
// ===== library: MasterCopy "SIKO_AG24_Tags_1" =====

VAR_GLOBAL   // PLC tag table "SIKO_AG24_Tags_1"
   "Drive1TargetValue" AT %QD2 : DWord;
   "Drive1ControlWord" AT %QW6 : Word;
   "Drive1DigitalOutputsControl" AT %QW8 : Word;
   "Drive1ActualValue" AT %ID2 : DWord;
   "Drive1GenericMappingChannel" AT %ID6 : DWord;
   "Drive1StatusWord" AT %IW10 : Word;
   "Drive1DigitalInputsState" AT %IW12 : Word;
END_VAR

// ===== library: MasterCopy "SIKO_AG24" =====

FUNCTION_BLOCK "SIKO_AG24"   // FB401, SCL
TITLE = SIKO_AG24
{ S7_Optimized_Access := 'FALSE' }
AUTHOR : SIKO_ch
FAMILY : AG24
NAME : 1.00
VERSION : 1.00
// Usable with AG24 Firmware Vers. A/V >= V1.06
   VAR_INPUT
      nTargetValue : DInt;
      bc00_Off1 : Bool;
      bc01_Off2 : Bool;
      bc02_Off3 : Bool;
      bc03_IntermediateStop : Bool;
      bc04_StartTravelJob : Bool;
      bc05_AckError : Bool;
      bc06_InchingMode1 : Bool;
      bc07_Inching2Pos : Bool;
      bc08_Inching2Neg : Bool;
      bc09_KeyEnable : Bool;
      bc10_MoveRelative : Bool;
      bc11 : Bool;
      bc12 : Bool;
      bc13 : Bool;
      bc14 : Bool;
      bc15_Cal : Bool;
      bcDigitalOutput1 : Bool;
      DC_nHwId : Hw_Io;
      DC_nStatusWord : Word;
      varrStatusWord AT DC_nStatusWord : Array[0..15] of Bool;
      DC_nActualValue : DWord;
      DC_nGenMapCh : DWord;
      DC_nDigitalInputsState : Word;
      varrDigitalInputsState AT DC_nDigitalInputsState : Array[0..15] of Bool;
      bcStartRead : Bool;
      bcStartWrite : Bool;
      bcStartCopy : Bool;
   END_VAR
   VAR_OUTPUT
      nActualValue : DInt;
      bs00_Supply : Bool;
      bs01_ReadinessToTravel : Bool;
      bs02_UpperLimit : Bool;
      bs03_LowerLimit : Bool;
      bs04_ActuatorTravels : Bool;
      bs05_InPos : Bool;
      bs06_ActiveTravelJob : Bool;
      bs07_Error : Bool;
      bs08_OperationEnabled : Bool;
      bs09_SwitchLock : Bool;
      bs10_TravelJobAck : Bool;
      bs11 : Bool;
      bs12_CurrentLimiting : Bool;
      bs13_LimitSwitch1 : Bool;
      bs14_LimitSwitch2 : Bool;
      bs15_CalAck : Bool;
      bsDigitalInput1 : Bool;
      bsDigitalInput2 : Bool;
      bsDigitalInput3 : Bool;
      bsDigitalInput4 : Bool;
      nGenMapCh : DInt;
      DC_nControlWord : Word;
      varrControlWord AT DC_nControlWord : Array[0..15] of Bool;
      DC_nTargetValue : DWord;
      DC_nDigitalOutputsControl : Word;
      varrDigitalOutputControl AT DC_nDigitalOutputsControl : Array[0..15] of Bool;
      bsBusy : Bool;
      bsError : Bool;
      bsDone : Bool;
      nStatus : DWord;
      nCounterRead : UInt;
      nCounterWrite : UInt;
      nCounterCopy : UInt;
   END_VAR
   VAR
      DC_DataBuffer : DWord;
      varrDataBuffer AT DC_DataBuffer : Array[0..3] of Byte;
      vbOsfReadBusy : Bool;
      vbMemReadBusy : Bool;
      vbOsfWriteBusy : Bool;
      vbMemWriteBusy : Bool;
      vbOsrStartRead : Bool;
      vbMemStartRead : Bool;
      vbOsrStartWrite : Bool;
      vbMemStartWrite : Bool;
      vbOsrStartCopy : Bool;
      vbMemStartCopy : Bool;
      vnReadCounter : UInt;
      vnWriteCounter : UInt;
      vnCopyCounter : UInt;
      fbRDREC1 : RDREC;
      vbReadValid : Bool;
      vbReadBusy : Bool;
      vbReadError : Bool;
      vnReadStatus : DWord;
      vnReadIndex : DInt;
      vbReadEnable : Bool;
      vnReadLength : UInt;
      vnReadState : UInt;
      fbWRREC_1 : WRREC;
      vbWriteDone : Bool;
      vbWriteBusy : Bool;
      vbWriteError : Bool;
      vnWriteStatus : DWord;
      vnWriteIndex : DInt;
      vbWriteEnable : Bool;
      vnWriteLength : UInt;
      vnWriteState : UInt;
      vnCopyState : UInt;
      p0221_ServiceInterfaceBaudRate_r : USInt;
      p0221_ServiceInterfaceBaudRate_w : USInt := 1;
      p0222_GenMapParam_r : USInt;
      p0222_GenMapParam_w : USInt := 0;
      p0241_PeakCurrentLimit_r : Int;
      p0241_PeakCurrentLimit_w : Int := 12000;
      p0242_PeakCurrentTime_r : Int;
      p0242_PeakCurrentTime_w : Int := 40;
      p0243_ContinuousCurrent_r : Int;
      p0243_ContinuousCurrent_w : Int := 7500;
      p0301_DigitalOutput1Functionality_r : USInt;
      p0301_DigitalOutput1Functionality_w : USInt := 0;
      p0302_DigitalOutputFunctionalitiesState_r : UDInt;
      p0303_DigitalOutputsPolarity_r : USInt;
      p0303_DigitalOutputsPolarity_w : USInt := 0;
      p0401_DigitalInput1Functionality_r : USInt;
      p0401_DigitalInput1Functionality_w : USInt := 0;
      p0402_DigitalInput2Functionality_r : USInt;
      p0402_DigitalInput2Functionality_w : USInt := 0;
      p0403_DigitalInput3Functionality_r : USInt;
      p0403_DigitalInput3Functionality_w : USInt := 0;
      p0404_DigitalInput4Functionality_r : USInt;
      p0404_DigitalInput4Functionality_w : USInt := 0;
      p0405_DigitalInputFunctionalitiesState_r : UDInt;
      p0406_DigitalInputsPolarity_r : USInt;
      p0406_DigitalInputsPolarity_w : USInt := 0;
      p0601_ControllerParameterP_r : Int;
      p0601_ControllerParameterP_w : Int := 300;
      p0602_ControllerParameterI_r : Int;
      p0602_ControllerParameterI_w : Int := 2;
      p0603_ControllerParameterD_r : Int;
      p0603_ControllerParameterD_w : Int := 0;
      p0604_APos_r : Int;
      p0604_APos_w : Int := 50;
      p0605_VPos_r : Int;
      p0605_VPos_w : Int := 10;
      p0606_DPos_r : Int;
      p0606_DPos_w : Int := 101;
      p0607_ARot_r : Int;
      p0607_ARot_w : Int := 50;
      p0608_AInch_r : Int;
      p0608_AInch_w : Int := 50;
      p0609_VInch_r : Int;
      p0609_VInch_w : Int := 10;
      p060A_PosWindow_r : Int;
      p060A_PosWindow_w : Int := 10;
      p060B_GearRatioNumerator_r : Int;
      p060B_GearRatioNumerator_w : Int := 1;
      p060C_GearRatioDenominator_r : Int;
      p060C_GearRatioDenominator_w : Int := 1;
      p060D_SpindlePitch_r : DInt;
      p060D_SpindlePitch_w : DInt := 0;
      p060E_CalibrationValue_r : DInt;
      p060E_CalibrationValue_w : DInt := 0;
      p060F_SoftwareLimit1_r : DInt;
      p060F_SoftwareLimit1_w : DInt := 999999;
      p0610_SoftwareLimit2_r : DInt;
      p0610_SoftwareLimit2_w : DInt := -199999;
      p0611_DeltaInch_r : DInt;
      p0611_DeltaInch_w : DInt := 1024;
      p0612_SenseOfRotation_r : USInt;
      p0612_SenseOfRotation_w : USInt := 0;
      p0613_PosType_r : USInt;
      p0613_PosType_w : USInt := 0;
      p0614_OperatingMode_r : USInt;
      p0614_OperatingMode_w : USInt := 0;
      p0615_Inching2StopMode_r : USInt;
      p0615_Inching2StopMode_w : USInt := 0;
      p0616_InposMode_r : USInt;
      p0616_InposMode_w : USInt := 0;
      p0617_LoopLength_r : Int;
      p0617_LoopLength_w : Int := 512;
      p0618_ContouringErrorLimit_r : Int;
      p0618_ContouringErrorLimit_w : Int := 1024;
      p061A_Inching2Offset_r : USInt;
      p061A_Inching2Offset_w : USInt := 100;
      p061B_Inching2AccelerationType_r : USInt;
      p061B_Inching2AccelerationType_w : USInt := 0;
      p061C_OffsetValue_r : DInt;
      p061C_OffsetValue_w : DInt := 0;
      p0701_DisplayDivisor_r : USInt;
      p0701_DisplayDivisor_w : USInt := 0;
      p0702_DisplayDivisorApplication_r : USInt;
      p0702_DisplayDivisorApplication_w : USInt := 0;
      p0703_DisplayOrientation_r : USInt;
      p0703_DisplayOrientation_w : USInt := 0;
      p0704_DecimalPlaces_r : USInt;
      p0704_DecimalPlaces_w : USInt := 0;
      p0705_DirectionIndicationFunction_r : USInt;
      p0705_DirectionIndicationFunction_w : USInt := 0;
      p0706_Display2ndLine_r : USInt;
      p0706_Display2ndLine_w : USInt := 0;
      p0707_KeyEnableTime_r : USInt;
      p0707_KeyEnableTime_w : USInt := 3;
      p0708_KeyFunctionEnable_r : USInt;
      p0708_KeyFunctionEnable_w : USInt := 0;
      p0709_PinChange_r : DInt;
      p0709_PinChange_w : DInt := 0;
      p0801_TalTrigger_r : Int;
      p0801_TalTrigger_w : Int := 0;
      p0802_TalDirection_r : USInt;
      p0802_TalDirection_w : USInt := 0;
      p0922_PcmPosition1_r : DInt;
      p0922_PcmPosition1_w : DInt := 0;
      p0923_PcmPosition2_r : DInt;
      p0923_PcmPosition2_w : DInt := 0;
      p0924_PcmPosition3_r : DInt;
      p0924_PcmPosition3_w : DInt := 0;
      p0925_PcmPosition4_r : DInt;
      p0925_PcmPosition4_w : DInt := 0;
      p0926_PcmPosition5_r : DInt;
      p0926_PcmPosition5_w : DInt := 0;
      p0927_PcmPosition6_r : DInt;
      p0927_PcmPosition6_w : DInt := 0;
      p0928_PcmPosition7_r : DInt;
      p0928_PcmPosition7_w : DInt := 0;
      p0942_PcmAcceleration1_r : Int;
      p0942_PcmAcceleration1_w : Int := 50;
      p0943_PcmAcceleration2_r : Int;
      p0943_PcmAcceleration2_w : Int := 50;
      p0944_PcmAcceleration3_r : Int;
      p0944_PcmAcceleration3_w : Int := 50;
      p0945_PcmAcceleration4_r : Int;
      p0945_PcmAcceleration4_w : Int := 50;
      p0946_PcmAcceleration5_r : Int;
      p0946_PcmAcceleration5_w : Int := 50;
      p0947_PcmAcceleration6_r : Int;
      p0947_PcmAcceleration6_w : Int := 50;
      p0948_PcmAcceleration7_r : Int;
      p0948_PcmAcceleration7_w : Int := 50;
      p0962_PcmVelocity1_r : Int;
      p0962_PcmVelocity1_w : Int := 10;
      p0963_PcmVelocity2_r : Int;
      p0963_PcmVelocity2_w : Int := 10;
      p0964_PcmVelocity3_r : Int;
      p0964_PcmVelocity3_w : Int := 10;
      p0965_PcmVelocity4_r : Int;
      p0965_PcmVelocity4_w : Int := 10;
      p0966_PcmVelocity5_r : Int;
      p0966_PcmVelocity5_w : Int := 10;
      p0967_PcmVelocity6_r : Int;
      p0967_PcmVelocity6_w : Int := 10;
      p0968_PcmVelocity7_r : Int;
      p0968_PcmVelocity7_w : Int := 10;
      p0982_PcmDeceleration1_r : Int;
      p0982_PcmDeceleration1_w : Int := 101;
      p0983_PcmDeceleration2_r : Int;
      p0983_PcmDeceleration2_w : Int := 101;
      p0984_PcmDeceleration3_r : Int;
      p0984_PcmDeceleration3_w : Int := 101;
      p0985_PcmDeceleration4_r : Int;
      p0985_PcmDeceleration4_w : Int := 101;
      p0986_PcmDeceleration5_r : Int;
      p0986_PcmDeceleration5_w : Int := 101;
      p0987_PcmDeceleration6_r : Int;
      p0987_PcmDeceleration6_w : Int := 101;
      p0988_PcmDeceleration7_r : Int;
      p0988_PcmDeceleration7_w : Int := 101;
      p0A01_OutputStageTemperature_r : Int;
      p0A02_VoltageOfControl_r : Int;
      p0A03_VoltageOfOutputStage_r : Int;
      p0A05_MotorCurrent_r : Int;
      p0A06_ActualPosition_r : DInt;
      p0A07_ActualRotationalSpeed_r : Int;
      p0A08_SerialNumber_r : DInt;
      p0A09_ProductionDate_r : DInt;
      p0A0A_SwMotorController_r : DInt;
      p0A0B_GearReduction_r : Int;
      p0A0C_SystemStatusWord_r : UInt;
      p0A0D_EncoderResolution_r : Int;
      p0A0E_DeviceId_r : USInt;
      p0A0F_VirtualMotorTemperature_r : Int;
      p0A10_OutputStageOverload_r : USInt;
      p0A11_ActualContouringError_r : DInt;
      p0B01_NumberOfErrors_r : USInt;
      p0B02_ErrorNumber1_r : USInt;
      p0B03_ErrorNumber2_r : USInt;
      p0B04_ErrorNumber3_r : USInt;
      p0B05_ErrorNumber4_r : USInt;
      p0B06_ErrorNumber5_r : USInt;
      p0B07_ErrorNumber6_r : USInt;
      p0B08_ErrorNumber7_r : USInt;
      p0B09_ErrorNumber8_r : USInt;
      p0B0A_ErrorNumber9_r : USInt;
      p0B0B_ErrorNumber10_r : USInt;
      p0B21_Configuration_r : UInt;
      p0B21_Configuration_w : UInt := 15;
      p0C01_Scommand_r : USInt;
      p0C01_Scommand_w : USInt := 0;
   END_VAR
BEGIN
   ////////////////////////////////////////////////////////////////////////////////////
   // Version history
   ////////////////////////////////////////////////////////////////////////////////////
   // Date        | Vers. | created               | Author          | Remark
   // dd.mm.yyyy  |       | with                  |                 | 
   // ---------------------------------------------------------------------------------
   // 01.08.2017  | 0.01  | TIA V13 SP1           | SIKO GmbH / ch  | alpha
   // 02.08.2017  | 0.02  | TIA V13 SP1           | SIKO GmbH / ch  | beta
   // 10.08.2017  | 0.03  | TIA V13 SP1           | SIKO GmbH / ch  | RC
   // 28.06.2018  | 1.00  | TIA V14 SP1 Upd5      | SIKO GmbH / ch  | Release
   ////////////////////////////////////////////////////////////////////////////////////

   // Actual Value
   #nActualValue := DWORD_TO_DINT(IN := #DC_nActualValue);

   // Generic Mapping Channel
   #nGenMapCh := DWORD_TO_DINT(IN := #DC_nGenMapCh);

   // Status Word Bits
   #bs00_Supply := #varrStatusWord[8];
   #bs01_ReadinessToTravel := #varrStatusWord[9];
   #bs02_UpperLimit := #varrStatusWord[10];
   #bs03_LowerLimit := #varrStatusWord[11];
   #bs04_ActuatorTravels := #varrStatusWord[12];
   #bs05_InPos := #varrStatusWord[13];
   #bs06_ActiveTravelJob := #varrStatusWord[14];
   #bs07_Error := #varrStatusWord[15];
   #bs08_OperationEnabled := #varrStatusWord[0];
   #bs09_SwitchLock := #varrStatusWord[1];
   #bs10_TravelJobAck := #varrStatusWord[2];
   #bs11 := #varrStatusWord[3];
   #bs12_CurrentLimiting := #varrStatusWord[4];
   #bs13_LimitSwitch1 := #varrStatusWord[5];
   #bs14_LimitSwitch2 := #varrStatusWord[6];
   #bs15_CalAck := #varrStatusWord[7];

   // Digital Inputs Status Bits
   #bsDigitalInput1 := #varrDigitalInputsState[8];
   #bsDigitalInput2 := #varrDigitalInputsState[9];
   #bsDigitalInput3 := #varrDigitalInputsState[10];
   #bsDigitalInput4 := #varrDigitalInputsState[11];

   // Target Value
   #DC_nTargetValue := DINT_TO_DWORD(IN := #nTargetValue);

   // Control Word Bits 
   #varrControlWord[8] := #bc00_Off1;
   #varrControlWord[9] := #bc01_Off2;
   #varrControlWord[10] := #bc02_Off3;
   #varrControlWord[11] := #bc03_IntermediateStop;
   #varrControlWord[12] := #bc04_StartTravelJob;
   #varrControlWord[13] := #bc05_AckError;
   #varrControlWord[14] := #bc06_InchingMode1;
   #varrControlWord[15] := #bc07_Inching2Pos;
   #varrControlWord[0] := #bc08_Inching2Neg;
   #varrControlWord[1] := #bc09_KeyEnable;
   #varrControlWord[2] := #bc10_MoveRelative;
   #varrControlWord[3] := #bc11;
   #varrControlWord[4] := #bc12;
   #varrControlWord[5] := #bc13;
   #varrControlWord[6] := #bc14;
   #varrControlWord[7] := #bc15_Cal;

   // Digital Output Control Bit 
   #varrDigitalOutputControl[8] := #bcDigitalOutput1;

   // Handle Parameter Read Command
   CASE #vnReadState OF
     0: // wait for rising edge at input bcStartRead
       IF #vbOsrStartRead AND (#vnWriteState = 0) AND (#vnCopyState = 0) THEN
         #bsBusy := TRUE;
         #bsError := FALSE;
         #bsDone := FALSE;
         #nStatus := 0;
         #nCounterRead := 0;
         #vnReadCounter := 0;
         #vnReadState := 1;
       END_IF;
     1: // Start RDREC
       #vnReadCounter := #vnReadCounter + 1;
       IF (#vnReadCounter > 109) THEN
       (* end of read cycle *)
         #bsBusy := FALSE;
         #bsError := FALSE;
         #bsDone := TRUE;
         #nStatus := 0;
         #nCounterRead := 0;
         #vnReadCounter := 0;
         #vnReadState := 0;
       ELSE
       (* output counter_read *)
         #nCounterRead := #vnReadCounter;
         CASE #vnReadCounter OF
           1:  (* p0221_ServiceInterfaceBaudrate *)
             #vnReadIndex := 545;
             #vbReadEnable := TRUE;
           2:  (* p0222_GenMapParam *)
             #vnReadIndex := 546;
             #vbReadEnable := TRUE;
           3:  (* p0241_PeakCurrentLimit *)
             #vnReadIndex := 577;
             #vbReadEnable := TRUE;
           4:  (* p0242_PeakCurrentTime *)
             #vnReadIndex := 578;
             #vbReadEnable := TRUE;
           5:  (* p0243_ContinuousCurrent *)
             #vnReadIndex := 579;
             #vbReadEnable := TRUE;
           6:  (* p0301_DigitalOutput1Functionality *)
             #vnReadIndex := 769;
             #vbReadEnable := TRUE;
           7:  (* p0302_DigitalOutputFunctionalitiesState *)
             #vnReadIndex := 770;
             #vbReadEnable := TRUE;
           8:  (* p0303_DigitalOutputsPolarity *)
             #vnReadIndex := 771;
             #vbReadEnable := TRUE;
           9:  (* p0401_DigitalInput1Functionality *)
             #vnReadIndex := 1025;
             #vbReadEnable := TRUE;
           10:  (* p0402_DigitalInput2Functionality *)
             #vnReadIndex := 1026;
             #vbReadEnable := TRUE;
           11:  (* p0403_DigitalInput3Functionality *)
             #vnReadIndex := 1027;
             #vbReadEnable := TRUE;
           12:  (* p0404_DigitalInput4Functionality *)
             #vnReadIndex := 1028;
             #vbReadEnable := TRUE;
           13:  (* p0405_DigitalInputFunctionalitiesState *)
             #vnReadIndex := 1029;
             #vbReadEnable := TRUE;
           14:  (* p0406_DigitalInputsPolarity *)
             #vnReadIndex := 1030;
             #vbReadEnable := TRUE;
           15:  (* p0601_ControllerParameterP *)
             #vnReadIndex := 1537;
             #vbReadEnable := TRUE;
           16:  (* p0602_ControllerParameterI *)
             #vnReadIndex := 1538;
             #vbReadEnable := TRUE;
           17:  (* p0603_ControllerParameterD *)
             #vnReadIndex := 1539;
             #vbReadEnable := TRUE;
           18:  (* p0604_APos *)
             #vnReadIndex := 1540;
             #vbReadEnable := TRUE;
           19:  (* p0605_VPos *)
             #vnReadIndex := 1541;
             #vbReadEnable := TRUE;
           20:  (* p0606_DPos *)
             #vnReadIndex := 1542;
             #vbReadEnable := TRUE;
           21:  (* p0607_ARot *)
             #vnReadIndex := 1543;
             #vbReadEnable := TRUE;
           22:  (* p0608_AInch *)
             #vnReadIndex := 1544;
             #vbReadEnable := TRUE;
           23:  (* p0609_VInch *)
             #vnReadIndex := 1545;
             #vbReadEnable := TRUE;
           24:  (* p060A_PosWindow *)
             #vnReadIndex := 1546;
             #vbReadEnable := TRUE;
           25:  (* p060B_GearRatioNumerator *)
             #vnReadIndex := 1547;
             #vbReadEnable := TRUE;
           26:  (* p060C_GearRatioDenominator *)
             #vnReadIndex := 1548;
             #vbReadEnable := TRUE;
           27:  (* p060D_SpindlePitch *)
             #vnReadIndex := 1549;
             #vbReadEnable := TRUE;
           28:  (* p060E_CalibrationValue *)
             #vnReadIndex := 1550;
             #vbReadEnable := TRUE;
           29:  (* p060F_SoftwareLimit1 *)
             #vnReadIndex := 1551;
             #vbReadEnable := TRUE;
           30:  (* p0610_SoftwareLimit2 *)
             #vnReadIndex := 1552;
             #vbReadEnable := TRUE;
           31:  (* p0611_DeltaInch *)
             #vnReadIndex := 1553;
             #vbReadEnable := TRUE;
           32:  (* p0612_SenseOfRotation *)
             #vnReadIndex := 1554;
             #vbReadEnable := TRUE;
           33:  (* p0613_PosType *)
             #vnReadIndex := 1555;
             #vbReadEnable := TRUE;
           34:  (* p0614_OperatingMode *)
             #vnReadIndex := 1556;
             #vbReadEnable := TRUE;
           35:  (* p0615_Inching2StopMode *)
             #vnReadIndex := 1557;
             #vbReadEnable := TRUE;
           36:  (* p0616_InposMode *)
             #vnReadIndex := 1558;
             #vbReadEnable := TRUE;
           37:  (* p0617_LoopLength *)
             #vnReadIndex := 1559;
             #vbReadEnable := TRUE;
           38:  (* p0618_ContouringErrorLimit *)
             #vnReadIndex := 1560;
             #vbReadEnable := TRUE;
           39:  (* p061A_Inching2Offset *)
             #vnReadIndex := 1562;
             #vbReadEnable := TRUE;
           40:  (* p061B_Inching2AccelerationType *)
             #vnReadIndex := 1563;
             #vbReadEnable := TRUE;
           41:  (* p061C_OffsetValue *)
             #vnReadIndex := 1564;
             #vbReadEnable := TRUE;
           42:  (* p0701_DisplayDivisor *)
             #vnReadIndex := 1793;
             #vbReadEnable := TRUE;
           43:  (* p0702_DisplayDivisorApplication *)
             #vnReadIndex := 1794;
             #vbReadEnable := TRUE;
           44:  (* p0703_DisplayOrientation *)
             #vnReadIndex := 1795;
             #vbReadEnable := TRUE;
           45:  (* p0704_DecimalPlaces *)
             #vnReadIndex := 1796;
             #vbReadEnable := TRUE;
           46:  (* p0705_DirectionIndicationFunction *)
             #vnReadIndex := 1797;
             #vbReadEnable := TRUE;
           47:  (* p0706_Display2ndLine *)
             #vnReadIndex := 1798;
             #vbReadEnable := TRUE;
           48:  (* p0707_KeyEnableTime *)
             #vnReadIndex := 1799;
             #vbReadEnable := TRUE;
           49:  (* p0708_KeyFunctionEnable *)
             #vnReadIndex := 1800;
             #vbReadEnable := TRUE;
           50:  (* p0709_PinChange *)
             #vnReadIndex := 1801;
             #vbReadEnable := TRUE;
           51:  (* p0801_TalTrigger *)
             #vnReadIndex := 2049;
             #vbReadEnable := TRUE;
           52:  (* p0802_TalDirection *)
             #vnReadIndex := 2050;
             #vbReadEnable := TRUE;
           53:  (* p0922_PcmPosition1 *)
             #vnReadIndex := 2338;
             #vbReadEnable := TRUE;
           54:  (* p0923_PcmPosition2 *)
             #vnReadIndex := 2339;
             #vbReadEnable := TRUE;
           55:  (* p0924_PcmPosition3 *)
             #vnReadIndex := 2340;
             #vbReadEnable := TRUE;
           56:  (* p0925_PcmPosition4 *)
             #vnReadIndex := 2341;
             #vbReadEnable := TRUE;
           57:  (* p0926_PcmPosition5 *)
             #vnReadIndex := 2342;
             #vbReadEnable := TRUE;
           58:  (* p0927_PcmPosition6 *)
             #vnReadIndex := 2343;
             #vbReadEnable := TRUE;
           59:  (* p0928_PcmPosition7 *)
             #vnReadIndex := 2344;
             #vbReadEnable := TRUE;
           60:  (* p0942_PcmAcceleration1 *)
             #vnReadIndex := 2370;
             #vbReadEnable := TRUE;
           61:  (* p0943_PcmAcceleration2 *)
             #vnReadIndex := 2371;
             #vbReadEnable := TRUE;
           62:  (* p0944_PcmAcceleration3 *)
             #vnReadIndex := 2372;
             #vbReadEnable := TRUE;
           63:  (* p0945_PcmAcceleration4 *)
             #vnReadIndex := 2373;
             #vbReadEnable := TRUE;
           64:  (* p0946_PcmAcceleration5 *)
             #vnReadIndex := 2374;
             #vbReadEnable := TRUE;
           65:  (* p0947_PcmAcceleration6 *)
             #vnReadIndex := 2375;
             #vbReadEnable := TRUE;
           66:  (* p0948_PcmAcceleration7 *)
             #vnReadIndex := 2376;
             #vbReadEnable := TRUE;
           67:  (* p0962_PcmVelocity1 *)
             #vnReadIndex := 2402;
             #vbReadEnable := TRUE;
           68:  (* p0963_PcmVelocity2 *)
             #vnReadIndex := 2403;
             #vbReadEnable := TRUE;
           69:  (* p0964_PcmVelocity3 *)
             #vnReadIndex := 2404;
             #vbReadEnable := TRUE;
           70:  (* p0965_PcmVelocity4 *)
             #vnReadIndex := 2405;
             #vbReadEnable := TRUE;
           71:  (* p0966_PcmVelocity5 *)
             #vnReadIndex := 2406;
             #vbReadEnable := TRUE;
           72:  (* p0967_PcmVelocity6 *)
             #vnReadIndex := 2407;
             #vbReadEnable := TRUE;
           73:  (* p0968_PcmVelocity7 *)
             #vnReadIndex := 2408;
             #vbReadEnable := TRUE;
           74:  (* p0982_PcmDeceleration1 *)
             #vnReadIndex := 2434;
             #vbReadEnable := TRUE;
           75:  (* p0983_PcmDeceleration2 *)
             #vnReadIndex := 2435;
             #vbReadEnable := TRUE;
           76:  (* p0984_PcmDeceleration3 *)
             #vnReadIndex := 2436;
             #vbReadEnable := TRUE;
           77:  (* p0985_PcmDeceleration4 *)
             #vnReadIndex := 2437;
             #vbReadEnable := TRUE;
           78:  (* p0986_PcmDeceleration5 *)
             #vnReadIndex := 2438;
             #vbReadEnable := TRUE;
           79:  (* p0987_PcmDeceleration6 *)
             #vnReadIndex := 2439;
             #vbReadEnable := TRUE;
           80:  (* p0988_PcmDeceleration7 *)
             #vnReadIndex := 2440;
             #vbReadEnable := TRUE;
           81:  (* p0A01_OutputStageTemperature *)
             #vnReadIndex := 2561;
             #vbReadEnable := TRUE;
           82:  (* p0A02_VoltageOfControl *)
             #vnReadIndex := 2562;
             #vbReadEnable := TRUE;
           83:  (* p0A03_VoltageOfOutputStage *)
             #vnReadIndex := 2563;
             #vbReadEnable := TRUE;
           84:  (* p0A05_MotorCurrent *)
             #vnReadIndex := 2565;
             #vbReadEnable := TRUE;
           85:  (* p0A06_ActualPosition *)
             #vnReadIndex := 2566;
             #vbReadEnable := TRUE;
           86:  (* p0A07_ActualRotationalSpeed *)
             #vnReadIndex := 2567;
             #vbReadEnable := TRUE;
           87:  (* p0A08_SerialNumber *)
             #vnReadIndex := 2568;
             #vbReadEnable := TRUE;
           88:  (* p0A09_ProductionDate *)
             #vnReadIndex := 2569;
             #vbReadEnable := TRUE;
           89:  (* p0A0A_SwMotorController *)
             #vnReadIndex := 2570;
             #vbReadEnable := TRUE;
           90:  (* p0A0B_GearReduction *)
             #vnReadIndex := 2571;
             #vbReadEnable := TRUE;
           91:  (* p0A0C_SystemStatusWord *)
             #vnReadIndex := 2572;
             #vbReadEnable := TRUE;
           92:  (* p0A0D_EncoderResolution *)
             #vnReadIndex := 2573;
             #vbReadEnable := TRUE;
           93:  (* p0A0E_DeviceId *)
             #vnReadIndex := 2574;
             #vbReadEnable := TRUE;
           94:  (* p0A0F_VirtualMotorTemperature *)
             #vnReadIndex := 2575;
             #vbReadEnable := TRUE;
           95:  (* p0A10_OutputStageOverload *)
             #vnReadIndex := 2576;
             #vbReadEnable := TRUE;
           96:  (* p0A11_ActualContouringError *)
             #vnReadIndex := 2577;
             #vbReadEnable := TRUE;
           97:  (* p0B01_NumberOfErrors *)
             #vnReadIndex := 2817;
             #vbReadEnable := TRUE;
           98:  (* p0B02_ErrorNumber1 *)
             #vnReadIndex := 2818;
             #vbReadEnable := TRUE;
           99:  (* p0B03_ErrorNumber2 *)
             #vnReadIndex := 2819;
             #vbReadEnable := TRUE;
           100:  (* p0B04_ErrorNumber3 *)
             #vnReadIndex := 2820;
             #vbReadEnable := TRUE;
           101:  (* p0B05_ErrorNumber4 *)
             #vnReadIndex := 2821;
             #vbReadEnable := TRUE;
           102:  (* p0B06_ErrorNumber5 *)
             #vnReadIndex := 2822;
             #vbReadEnable := TRUE;
           103:  (* p0B07_ErrorNumber6 *)
             #vnReadIndex := 2823;
             #vbReadEnable := TRUE;
           104:  (* p0B08_ErrorNumber7 *)
             #vnReadIndex := 2824;
             #vbReadEnable := TRUE;
           105:  (* p0B09_ErrorNumber8 *)
             #vnReadIndex := 2825;
             #vbReadEnable := TRUE;
           106:  (* p0B0A_ErrorNumber9 *)
             #vnReadIndex := 2826;
             #vbReadEnable := TRUE;
           107:  (* p0B0B_ErrorNumber10 *)
             #vnReadIndex := 2827;
             #vbReadEnable := TRUE;
           108:  (* p0B21_Configuration *)
             #vnReadIndex := 2849;
             #vbReadEnable := TRUE;
           109:  (* p0C01_Scommand *)
             #vnReadIndex := 3073;
             #vbReadEnable := TRUE;
         END_CASE;
         #vnReadState := 2;
       END_IF;
     2: // wait for end of RDREC
       IF #vbOsfReadBusy THEN
         #vnReadState := 3;
       END_IF;
     3: // Check for errors, copy output
       #vbReadEnable := FALSE;
       IF #vbReadError THEN
         #bsBusy := FALSE;
         #bsError := TRUE;
         #bsDone := FALSE;
         #nStatus := #vnReadStatus;
         #vnReadCounter := 0;
         #vnReadState := 0;
       ELSIF #vbReadValid THEN
       (* Data Valid *)
         #nStatus := #vnReadStatus;

         CASE #vnReadCounter OF
           1:
             #p0221_ServiceInterfaceBaudRate_r := DWORD_TO_USINT(SHR(IN := #DC_DataBuffer, N := 24));
           2:
             #p0222_GenMapParam_r := DWORD_TO_USINT(SHR(IN := #DC_DataBuffer, N := 24));
           3:
             #p0241_PeakCurrentLimit_r := DWORD_TO_INT(SHR(IN := #DC_DataBuffer, N := 16));
           4:
             #p0242_PeakCurrentTime_r := DWORD_TO_INT(SHR(IN := #DC_DataBuffer, N := 16));
           5:
             #p0243_ContinuousCurrent_r := DWORD_TO_INT(SHR(IN := #DC_DataBuffer, N := 16));
           6:
             #p0301_DigitalOutput1Functionality_r := DWORD_TO_USINT(SHR(IN := #DC_DataBuffer, N := 24));
           7:
             #p0302_DigitalOutputFunctionalitiesState_r := DWORD_TO_UDINT(SHR(IN := #DC_DataBuffer, N := 0));
           8:
             #p0303_DigitalOutputsPolarity_r := DWORD_TO_USINT(SHR(IN := #DC_DataBuffer, N := 24));
           9:
             #p0401_DigitalInput1Functionality_r := DWORD_TO_USINT(SHR(IN := #DC_DataBuffer, N := 24));
           10:
             #p0402_DigitalInput2Functionality_r := DWORD_TO_USINT(SHR(IN := #DC_DataBuffer, N := 24));
           11:
             #p0403_DigitalInput3Functionality_r := DWORD_TO_USINT(SHR(IN := #DC_DataBuffer, N := 24));
           12:
             #p0404_DigitalInput4Functionality_r := DWORD_TO_USINT(SHR(IN := #DC_DataBuffer, N := 24));
           13:
             #p0405_DigitalInputFunctionalitiesState_r := DWORD_TO_UDINT(SHR(IN := #DC_DataBuffer, N := 0));
           14:
             #p0406_DigitalInputsPolarity_r := DWORD_TO_USINT(SHR(IN := #DC_DataBuffer, N := 24));
           15:
             #p0601_ControllerParameterP_r := DWORD_TO_INT(SHR(IN := #DC_DataBuffer, N := 16));
           16:
             #p0602_ControllerParameterI_r := DWORD_TO_INT(SHR(IN := #DC_DataBuffer, N := 16));
           17:
             #p0603_ControllerParameterD_r := DWORD_TO_INT(SHR(IN := #DC_DataBuffer, N := 16));
           18:
             #p0604_APos_r := DWORD_TO_INT(SHR(IN := #DC_DataBuffer, N := 16));
           19:
             #p0605_VPos_r := DWORD_TO_INT(SHR(IN := #DC_DataBuffer, N := 16));
           20:
             #p0606_DPos_r := DWORD_TO_INT(SHR(IN := #DC_DataBuffer, N := 16));
           21:
             #p0607_ARot_r := DWORD_TO_INT(SHR(IN := #DC_DataBuffer, N := 16));
           22:
             #p0608_AInch_r := DWORD_TO_INT(SHR(IN := #DC_DataBuffer, N := 16));
           23:
             #p0609_VInch_r := DWORD_TO_INT(SHR(IN := #DC_DataBuffer, N := 16));
           24:
             #p060A_PosWindow_r := DWORD_TO_INT(SHR(IN := #DC_DataBuffer, N := 16));
           25:
             #p060B_GearRatioNumerator_r := DWORD_TO_INT(SHR(IN := #DC_DataBuffer, N := 16));
           26:
             #p060C_GearRatioDenominator_r := DWORD_TO_INT(SHR(IN := #DC_DataBuffer, N := 16));
           27:
             #p060D_SpindlePitch_r := DWORD_TO_DINT(SHR(IN := #DC_DataBuffer, N := 0));
           28:
             #p060E_CalibrationValue_r := DWORD_TO_DINT(SHR(IN := #DC_DataBuffer, N := 0));
           29:
             #p060F_SoftwareLimit1_r := DWORD_TO_DINT(SHR(IN := #DC_DataBuffer, N := 0));
           30:
             #p0610_SoftwareLimit2_r := DWORD_TO_DINT(SHR(IN := #DC_DataBuffer, N := 0));
           31:
             #p0611_DeltaInch_r := DWORD_TO_DINT(SHR(IN := #DC_DataBuffer, N := 0));
           32:
             #p0612_SenseOfRotation_r := DWORD_TO_USINT(SHR(IN := #DC_DataBuffer, N := 24));
           33:
             #p0613_PosType_r := DWORD_TO_USINT(SHR(IN := #DC_DataBuffer, N := 24));
           34:
             #p0614_OperatingMode_r := DWORD_TO_USINT(SHR(IN := #DC_DataBuffer, N := 24));
           35:
             #p0615_Inching2StopMode_r := DWORD_TO_USINT(SHR(IN := #DC_DataBuffer, N := 24));
           36:
             #p0616_InposMode_r := DWORD_TO_USINT(SHR(IN := #DC_DataBuffer, N := 24));
           37:
             #p0617_LoopLength_r := DWORD_TO_INT(SHR(IN := #DC_DataBuffer, N := 16));
           38:
             #p0618_ContouringErrorLimit_r := DWORD_TO_INT(SHR(IN := #DC_DataBuffer, N := 16));
           39:
             #p061A_Inching2Offset_r := DWORD_TO_USINT(SHR(IN := #DC_DataBuffer, N := 24));
           40:
             #p061B_Inching2AccelerationType_r := DWORD_TO_USINT(SHR(IN := #DC_DataBuffer, N := 24));
           41:
             #p061C_OffsetValue_r := DWORD_TO_DINT(SHR(IN := #DC_DataBuffer, N := 0));
           42:
             #p0701_DisplayDivisor_r := DWORD_TO_USINT(SHR(IN := #DC_DataBuffer, N := 24));
           43:
             #p0702_DisplayDivisorApplication_r := DWORD_TO_USINT(SHR(IN := #DC_DataBuffer, N := 24));
           44:
             #p0703_DisplayOrientation_r := DWORD_TO_USINT(SHR(IN := #DC_DataBuffer, N := 24));
           45:
             #p0704_DecimalPlaces_r := DWORD_TO_USINT(SHR(IN := #DC_DataBuffer, N := 24));
           46:
             #p0705_DirectionIndicationFunction_r := DWORD_TO_USINT(SHR(IN := #DC_DataBuffer, N := 24));
           47:
             #p0706_Display2ndLine_r := DWORD_TO_USINT(SHR(IN := #DC_DataBuffer, N := 24));
           48:
             #p0707_KeyEnableTime_r := DWORD_TO_USINT(SHR(IN := #DC_DataBuffer, N := 24));
           49:
             #p0708_KeyFunctionEnable_r := DWORD_TO_USINT(SHR(IN := #DC_DataBuffer, N := 24));
           50:
             #p0709_PinChange_r := DWORD_TO_DINT(SHR(IN := #DC_DataBuffer, N := 0));
           51:
             #p0801_TalTrigger_r := DWORD_TO_INT(SHR(IN := #DC_DataBuffer, N := 16));
           52:
             #p0802_TalDirection_r := DWORD_TO_USINT(SHR(IN := #DC_DataBuffer, N := 24));
           53:
             #p0922_PcmPosition1_r := DWORD_TO_DINT(SHR(IN := #DC_DataBuffer, N := 0));
           54:
             #p0923_PcmPosition2_r := DWORD_TO_DINT(SHR(IN := #DC_DataBuffer, N := 0));
           55:
             #p0924_PcmPosition3_r := DWORD_TO_DINT(SHR(IN := #DC_DataBuffer, N := 0));
           56:
             #p0925_PcmPosition4_r := DWORD_TO_DINT(SHR(IN := #DC_DataBuffer, N := 0));
           57:
             #p0926_PcmPosition5_r := DWORD_TO_DINT(SHR(IN := #DC_DataBuffer, N := 0));
           58:
             #p0927_PcmPosition6_r := DWORD_TO_DINT(SHR(IN := #DC_DataBuffer, N := 0));
           59:
             #p0928_PcmPosition7_r := DWORD_TO_DINT(SHR(IN := #DC_DataBuffer, N := 0));
           60:
             #p0942_PcmAcceleration1_r := DWORD_TO_INT(SHR(IN := #DC_DataBuffer, N := 16));
           61:
             #p0943_PcmAcceleration2_r := DWORD_TO_INT(SHR(IN := #DC_DataBuffer, N := 16));
           62:
             #p0944_PcmAcceleration3_r := DWORD_TO_INT(SHR(IN := #DC_DataBuffer, N := 16));
           63:
             #p0945_PcmAcceleration4_r := DWORD_TO_INT(SHR(IN := #DC_DataBuffer, N := 16));
           64:
             #p0946_PcmAcceleration5_r := DWORD_TO_INT(SHR(IN := #DC_DataBuffer, N := 16));
           65:
             #p0947_PcmAcceleration6_r := DWORD_TO_INT(SHR(IN := #DC_DataBuffer, N := 16));
           66:
             #p0948_PcmAcceleration7_r := DWORD_TO_INT(SHR(IN := #DC_DataBuffer, N := 16));
           67:
             #p0962_PcmVelocity1_r := DWORD_TO_INT(SHR(IN := #DC_DataBuffer, N := 16));
           68:
             #p0963_PcmVelocity2_r := DWORD_TO_INT(SHR(IN := #DC_DataBuffer, N := 16));
           69:
             #p0964_PcmVelocity3_r := DWORD_TO_INT(SHR(IN := #DC_DataBuffer, N := 16));
           70:
             #p0965_PcmVelocity4_r := DWORD_TO_INT(SHR(IN := #DC_DataBuffer, N := 16));
           71:
             #p0966_PcmVelocity5_r := DWORD_TO_INT(SHR(IN := #DC_DataBuffer, N := 16));
           72:
             #p0967_PcmVelocity6_r := DWORD_TO_INT(SHR(IN := #DC_DataBuffer, N := 16));
           73:
             #p0968_PcmVelocity7_r := DWORD_TO_INT(SHR(IN := #DC_DataBuffer, N := 16));
           74:
             #p0982_PcmDeceleration1_r := DWORD_TO_INT(SHR(IN := #DC_DataBuffer, N := 16));
           75:
             #p0983_PcmDeceleration2_r := DWORD_TO_INT(SHR(IN := #DC_DataBuffer, N := 16));
           76:
             #p0984_PcmDeceleration3_r := DWORD_TO_INT(SHR(IN := #DC_DataBuffer, N := 16));
           77:
             #p0985_PcmDeceleration4_r := DWORD_TO_INT(SHR(IN := #DC_DataBuffer, N := 16));
           78:
             #p0986_PcmDeceleration5_r := DWORD_TO_INT(SHR(IN := #DC_DataBuffer, N := 16));
           79:
             #p0987_PcmDeceleration6_r := DWORD_TO_INT(SHR(IN := #DC_DataBuffer, N := 16));
           80:
             #p0988_PcmDeceleration7_r := DWORD_TO_INT(SHR(IN := #DC_DataBuffer, N := 16));
           81:
             #p0A01_OutputStageTemperature_r := DWORD_TO_INT(SHR(IN := #DC_DataBuffer, N := 16));
           82:
             #p0A02_VoltageOfControl_r := DWORD_TO_INT(SHR(IN := #DC_DataBuffer, N := 16));
           83:
             #p0A03_VoltageOfOutputStage_r := DWORD_TO_INT(SHR(IN := #DC_DataBuffer, N := 16));
           84:
             #p0A05_MotorCurrent_r := DWORD_TO_INT(SHR(IN := #DC_DataBuffer, N := 16));
           85:
             #p0A06_ActualPosition_r := DWORD_TO_DINT(SHR(IN := #DC_DataBuffer, N := 0));
           86:
             #p0A07_ActualRotationalSpeed_r := DWORD_TO_INT(SHR(IN := #DC_DataBuffer, N := 16));
           87:
             #p0A08_SerialNumber_r := DWORD_TO_DINT(SHR(IN := #DC_DataBuffer, N := 0));
           88:
             #p0A09_ProductionDate_r := DWORD_TO_DINT(SHR(IN := #DC_DataBuffer, N := 0));
           89:
             #p0A0A_SwMotorController_r := DWORD_TO_DINT(SHR(IN := #DC_DataBuffer, N := 0));
           90:
             #p0A0B_GearReduction_r := DWORD_TO_INT(SHR(IN := #DC_DataBuffer, N := 16));
           91:
             #p0A0C_SystemStatusWord_r := DWORD_TO_UINT(SHR(IN := #DC_DataBuffer, N := 16));
           92:
             #p0A0D_EncoderResolution_r := DWORD_TO_INT(SHR(IN := #DC_DataBuffer, N := 16));
           93:
             #p0A0E_DeviceId_r := DWORD_TO_USINT(SHR(IN := #DC_DataBuffer, N := 24));
           94:
             #p0A0F_VirtualMotorTemperature_r := DWORD_TO_INT(SHR(IN := #DC_DataBuffer, N := 16));
           95:
             #p0A10_OutputStageOverload_r := DWORD_TO_USINT(SHR(IN := #DC_DataBuffer, N := 24));
           96:
             #p0A11_ActualContouringError_r := DWORD_TO_DINT(SHR(IN := #DC_DataBuffer, N := 0));
           97:
             #p0B01_NumberOfErrors_r := DWORD_TO_USINT(SHR(IN := #DC_DataBuffer, N := 24));
           98:
             #p0B02_ErrorNumber1_r := DWORD_TO_USINT(SHR(IN := #DC_DataBuffer, N := 24));
           99:
             #p0B03_ErrorNumber2_r := DWORD_TO_USINT(SHR(IN := #DC_DataBuffer, N := 24));
           100:
             #p0B04_ErrorNumber3_r := DWORD_TO_USINT(SHR(IN := #DC_DataBuffer, N := 24));
           101:
             #p0B05_ErrorNumber4_r := DWORD_TO_USINT(SHR(IN := #DC_DataBuffer, N := 24));
           102:
             #p0B06_ErrorNumber5_r := DWORD_TO_USINT(SHR(IN := #DC_DataBuffer, N := 24));
           103:
             #p0B07_ErrorNumber6_r := DWORD_TO_USINT(SHR(IN := #DC_DataBuffer, N := 24));
           104:
             #p0B08_ErrorNumber7_r := DWORD_TO_USINT(SHR(IN := #DC_DataBuffer, N := 24));
           105:
             #p0B09_ErrorNumber8_r := DWORD_TO_USINT(SHR(IN := #DC_DataBuffer, N := 24));
           106:
             #p0B0A_ErrorNumber9_r := DWORD_TO_USINT(SHR(IN := #DC_DataBuffer, N := 24));
           107:
             #p0B0B_ErrorNumber10_r := DWORD_TO_USINT(SHR(IN := #DC_DataBuffer, N := 24));
           108:
             #p0B21_Configuration_r := DWORD_TO_UINT(SHR(IN := #DC_DataBuffer, N := 16));
           109:
             #p0C01_Scommand_r := DWORD_TO_USINT(SHR(IN := #DC_DataBuffer, N := 24));
         END_CASE;
         #vnReadState := 1;
       END_IF;
   END_CASE;

   // Handle Parameter Write Command
   CASE #vnWriteState OF
     0: // wait for rising edge at input bcStartWrite
       IF #vbOsrStartWrite AND (#vnReadState = 0) AND (#vnCopyState = 0) THEN
         #bsBusy := TRUE;
         #bsError := FALSE;
         #bsDone := FALSE;
         #nStatus := 0;
         #nCounterWrite := 0;
         #vnWriteCounter := 0;
         #vnWriteState := 1;
       END_IF;
     1: // Start WRREC
       #vnWriteCounter := #vnWriteCounter + 1;
       IF (#vnWriteCounter > 80) THEN
         // End of write cycle
         #bsBusy := FALSE;
         #bsError := FALSE;
         #bsDone := TRUE;
         #nStatus := 0;
         #nCounterWrite := 0;
         #vnWriteCounter := 0;
         #vnWriteState := 0;
       ELSE
       (* output counter_write *)
         #nCounterWrite := #vnWriteCounter;
         CASE #vnWriteCounter OF
           1:
             IF #p0221_ServiceInterfaceBaudRate_w <> #p0221_ServiceInterfaceBaudRate_r THEN
               #vnWriteIndex := 545;
               #vnWriteLength := 1;
               #vbWriteEnable := TRUE;
               #DC_DataBuffer := SHL(IN := USINT_TO_DWORD(#p0221_ServiceInterfaceBaudRate_w), N := 24);
               #vnWriteState := 2;
             ELSE
               #vnWriteState := 1;
             END_IF;
           2:
             IF #p0222_GenMapParam_w <> #p0222_GenMapParam_r THEN
               #vnWriteIndex := 546;
               #vnWriteLength := 1;
               #vbWriteEnable := TRUE;
               #DC_DataBuffer := SHL(IN := USINT_TO_DWORD(#p0222_GenMapParam_w), N := 24);
               #vnWriteState := 2;
             ELSE
               #vnWriteState := 1;
             END_IF;
           3:
             IF #p0241_PeakCurrentLimit_w <> #p0241_PeakCurrentLimit_r THEN
               #vnWriteIndex := 577;
               #vnWriteLength := 2;
               #vbWriteEnable := TRUE;
               #DC_DataBuffer := SHL(IN := INT_TO_DWORD(#p0241_PeakCurrentLimit_w), N := 16);
               #vnWriteState := 2;
             ELSE
               #vnWriteState := 1;
             END_IF;
           4:
             IF #p0242_PeakCurrentTime_w <> #p0242_PeakCurrentTime_r THEN
               #vnWriteIndex := 578;
               #vnWriteLength := 2;
               #vbWriteEnable := TRUE;
               #DC_DataBuffer := SHL(IN := INT_TO_DWORD(#p0242_PeakCurrentTime_w), N := 16);
               #vnWriteState := 2;
             ELSE
               #vnWriteState := 1;
             END_IF;
           5:
             IF #p0243_ContinuousCurrent_w <> #p0243_ContinuousCurrent_r THEN
               #vnWriteIndex := 579;
               #vnWriteLength := 2;
               #vbWriteEnable := TRUE;
               #DC_DataBuffer := SHL(IN := INT_TO_DWORD(#p0243_ContinuousCurrent_w), N := 16);
               #vnWriteState := 2;
             ELSE
               #vnWriteState := 1;
             END_IF;
           6:
             IF #p0301_DigitalOutput1Functionality_w <> #p0301_DigitalOutput1Functionality_r THEN
               #vnWriteIndex := 769;
               #vnWriteLength := 1;
               #vbWriteEnable := TRUE;
               #DC_DataBuffer := SHL(IN := USINT_TO_DWORD(#p0301_DigitalOutput1Functionality_w), N := 24);
               #vnWriteState := 2;
             ELSE
               #vnWriteState := 1;
             END_IF;
           7:
             IF #p0303_DigitalOutputsPolarity_w <> #p0303_DigitalOutputsPolarity_r THEN
               #vnWriteIndex := 771;
               #vnWriteLength := 1;
               #vbWriteEnable := TRUE;
               #DC_DataBuffer := SHL(IN := USINT_TO_DWORD(#p0303_DigitalOutputsPolarity_w), N := 24);
               #vnWriteState := 2;
             ELSE
               #vnWriteState := 1;
             END_IF;
           8:
             IF #p0401_DigitalInput1Functionality_w <> #p0401_DigitalInput1Functionality_r THEN
               #vnWriteIndex := 1025;
               #vnWriteLength := 1;
               #vbWriteEnable := TRUE;
               #DC_DataBuffer := SHL(IN := USINT_TO_DWORD(#p0401_DigitalInput1Functionality_w), N := 24);
               #vnWriteState := 2;
             ELSE
               #vnWriteState := 1;
             END_IF;
           9:
             IF #p0402_DigitalInput2Functionality_w <> #p0402_DigitalInput2Functionality_r THEN
               #vnWriteIndex := 1026;
               #vnWriteLength := 1;
               #vbWriteEnable := TRUE;
               #DC_DataBuffer := SHL(IN := USINT_TO_DWORD(#p0402_DigitalInput2Functionality_w), N := 24);
               #vnWriteState := 2;
             ELSE
               #vnWriteState := 1;
             END_IF;
           10:
             IF #p0403_DigitalInput3Functionality_w <> #p0403_DigitalInput3Functionality_r THEN
               #vnWriteIndex := 1027;
               #vnWriteLength := 1;
               #vbWriteEnable := TRUE;
               #DC_DataBuffer := SHL(IN := USINT_TO_DWORD(#p0403_DigitalInput3Functionality_w), N := 24);
               #vnWriteState := 2;
             ELSE
               #vnWriteState := 1;
             END_IF;
           11:
             IF #p0404_DigitalInput4Functionality_w <> #p0404_DigitalInput4Functionality_r THEN
               #vnWriteIndex := 1028;
               #vnWriteLength := 1;
               #vbWriteEnable := TRUE;
               #DC_DataBuffer := SHL(IN := USINT_TO_DWORD(#p0404_DigitalInput4Functionality_w), N := 24);
               #vnWriteState := 2;
             ELSE
               #vnWriteState := 1;
             END_IF;
           12:
             IF #p0406_DigitalInputsPolarity_w <> #p0406_DigitalInputsPolarity_r THEN
               #vnWriteIndex := 1030;
               #vnWriteLength := 1;
               #vbWriteEnable := TRUE;
               #DC_DataBuffer := SHL(IN := USINT_TO_DWORD(#p0406_DigitalInputsPolarity_w), N := 24);
               #vnWriteState := 2;
             ELSE
               #vnWriteState := 1;
             END_IF;
           13:
             IF #p0601_ControllerParameterP_w <> #p0601_ControllerParameterP_r THEN
               #vnWriteIndex := 1537;
               #vnWriteLength := 2;
               #vbWriteEnable := TRUE;
               #DC_DataBuffer := SHL(IN := INT_TO_DWORD(#p0601_ControllerParameterP_w), N := 16);
               #vnWriteState := 2;
             ELSE
               #vnWriteState := 1;
             END_IF;
           14:
             IF #p0602_ControllerParameterI_w <> #p0602_ControllerParameterI_r THEN
               #vnWriteIndex := 1538;
               #vnWriteLength := 2;
               #vbWriteEnable := TRUE;
               #DC_DataBuffer := SHL(IN := INT_TO_DWORD(#p0602_ControllerParameterI_w), N := 16);
               #vnWriteState := 2;
             ELSE
               #vnWriteState := 1;
             END_IF;
           15:
             IF #p0603_ControllerParameterD_w <> #p0603_ControllerParameterD_r THEN
               #vnWriteIndex := 1539;
               #vnWriteLength := 2;
               #vbWriteEnable := TRUE;
               #DC_DataBuffer := SHL(IN := INT_TO_DWORD(#p0603_ControllerParameterD_w), N := 16);
               #vnWriteState := 2;
             ELSE
               #vnWriteState := 1;
             END_IF;
           16:
             IF #p0604_APos_w <> #p0604_APos_r THEN
               #vnWriteIndex := 1540;
               #vnWriteLength := 2;
               #vbWriteEnable := TRUE;
               #DC_DataBuffer := SHL(IN := INT_TO_DWORD(#p0604_APos_w), N := 16);
               #vnWriteState := 2;
             ELSE
               #vnWriteState := 1;
             END_IF;
           17:
             IF #p0605_VPos_w <> #p0605_VPos_r THEN
               #vnWriteIndex := 1541;
               #vnWriteLength := 2;
               #vbWriteEnable := TRUE;
               #DC_DataBuffer := SHL(IN := INT_TO_DWORD(#p0605_VPos_w), N := 16);
               #vnWriteState := 2;
             ELSE
               #vnWriteState := 1;
             END_IF;
           18:
             IF #p0606_DPos_w <> #p0606_DPos_r THEN
               #vnWriteIndex := 1542;
               #vnWriteLength := 2;
               #vbWriteEnable := TRUE;
               #DC_DataBuffer := SHL(IN := INT_TO_DWORD(#p0606_DPos_w), N := 16);
               #vnWriteState := 2;
             ELSE
               #vnWriteState := 1;
             END_IF;
           19:
             IF #p0607_ARot_w <> #p0607_ARot_r THEN
               #vnWriteIndex := 1543;
               #vnWriteLength := 2;
               #vbWriteEnable := TRUE;
               #DC_DataBuffer := SHL(IN := INT_TO_DWORD(#p0607_ARot_w), N := 16);
               #vnWriteState := 2;
             ELSE
               #vnWriteState := 1;
             END_IF;
           20:
             IF #p0608_AInch_w <> #p0608_AInch_r THEN
               #vnWriteIndex := 1544;
               #vnWriteLength := 2;
               #vbWriteEnable := TRUE;
               #DC_DataBuffer := SHL(IN := INT_TO_DWORD(#p0608_AInch_w), N := 16);
               #vnWriteState := 2;
             ELSE
               #vnWriteState := 1;
             END_IF;
           21:
             IF #p0609_VInch_w <> #p0609_VInch_r THEN
               #vnWriteIndex := 1545;
               #vnWriteLength := 2;
               #vbWriteEnable := TRUE;
               #DC_DataBuffer := SHL(IN := INT_TO_DWORD(#p0609_VInch_w), N := 16);
               #vnWriteState := 2;
             ELSE
               #vnWriteState := 1;
             END_IF;
           22:
             IF #p060A_PosWindow_w <> #p060A_PosWindow_r THEN
               #vnWriteIndex := 1546;
               #vnWriteLength := 2;
               #vbWriteEnable := TRUE;
               #DC_DataBuffer := SHL(IN := INT_TO_DWORD(#p060A_PosWindow_w), N := 16);
               #vnWriteState := 2;
             ELSE
               #vnWriteState := 1;
             END_IF;
           23:
             IF #p060B_GearRatioNumerator_w <> #p060B_GearRatioNumerator_r THEN
               #vnWriteIndex := 1547;
               #vnWriteLength := 2;
               #vbWriteEnable := TRUE;
               #DC_DataBuffer := SHL(IN := INT_TO_DWORD(#p060B_GearRatioNumerator_w), N := 16);
               #vnWriteState := 2;
             ELSE
               #vnWriteState := 1;
             END_IF;
           24:
             IF #p060C_GearRatioDenominator_w <> #p060C_GearRatioDenominator_r THEN
               #vnWriteIndex := 1548;
               #vnWriteLength := 2;
               #vbWriteEnable := TRUE;
               #DC_DataBuffer := SHL(IN := INT_TO_DWORD(#p060C_GearRatioDenominator_w), N := 16);
               #vnWriteState := 2;
             ELSE
               #vnWriteState := 1;
             END_IF;
           25:
             IF #p060D_SpindlePitch_w <> #p060D_SpindlePitch_r THEN
               #vnWriteIndex := 1549;
               #vnWriteLength := 4;
               #vbWriteEnable := TRUE;
               #DC_DataBuffer := SHL(IN := DINT_TO_DWORD(#p060D_SpindlePitch_w), N := 0);
               #vnWriteState := 2;
             ELSE
               #vnWriteState := 1;
             END_IF;
           26:
             IF #p060E_CalibrationValue_w <> #p060E_CalibrationValue_r THEN
               #vnWriteIndex := 1550;
               #vnWriteLength := 4;
               #vbWriteEnable := TRUE;
               #DC_DataBuffer := SHL(IN := DINT_TO_DWORD(#p060E_CalibrationValue_w), N := 0);
               #vnWriteState := 2;
             ELSE
               #vnWriteState := 1;
             END_IF;
           27:
             IF #p060F_SoftwareLimit1_w <> #p060F_SoftwareLimit1_r THEN
               #vnWriteIndex := 1551;
               #vnWriteLength := 4;
               #vbWriteEnable := TRUE;
               #DC_DataBuffer := SHL(IN := DINT_TO_DWORD(#p060F_SoftwareLimit1_w), N := 0);
               #vnWriteState := 2;
             ELSE
               #vnWriteState := 1;
             END_IF;
           28:
             IF #p0610_SoftwareLimit2_w <> #p0610_SoftwareLimit2_r THEN
               #vnWriteIndex := 1552;
               #vnWriteLength := 4;
               #vbWriteEnable := TRUE;
               #DC_DataBuffer := SHL(IN := DINT_TO_DWORD(#p0610_SoftwareLimit2_w), N := 0);
               #vnWriteState := 2;
             ELSE
               #vnWriteState := 1;
             END_IF;
           29:
             IF #p0611_DeltaInch_w <> #p0611_DeltaInch_r THEN
               #vnWriteIndex := 1553;
               #vnWriteLength := 4;
               #vbWriteEnable := TRUE;
               #DC_DataBuffer := SHL(IN := DINT_TO_DWORD(#p0611_DeltaInch_w), N := 0);
               #vnWriteState := 2;
             ELSE
               #vnWriteState := 1;
             END_IF;
           30:
             IF #p0612_SenseOfRotation_w <> #p0612_SenseOfRotation_r THEN
               #vnWriteIndex := 1554;
               #vnWriteLength := 1;
               #vbWriteEnable := TRUE;
               #DC_DataBuffer := SHL(IN := USINT_TO_DWORD(#p0612_SenseOfRotation_w), N := 24);
               #vnWriteState := 2;
             ELSE
               #vnWriteState := 1;
             END_IF;
           31:
             IF #p0613_PosType_w <> #p0613_PosType_r THEN
               #vnWriteIndex := 1555;
               #vnWriteLength := 1;
               #vbWriteEnable := TRUE;
               #DC_DataBuffer := SHL(IN := USINT_TO_DWORD(#p0613_PosType_w), N := 24);
               #vnWriteState := 2;
             ELSE
               #vnWriteState := 1;
             END_IF;
           32:
             IF #p0614_OperatingMode_w <> #p0614_OperatingMode_r THEN
               #vnWriteIndex := 1556;
               #vnWriteLength := 1;
               #vbWriteEnable := TRUE;
               #DC_DataBuffer := SHL(IN := USINT_TO_DWORD(#p0614_OperatingMode_w), N := 24);
               #vnWriteState := 2;
             ELSE
               #vnWriteState := 1;
             END_IF;
           33:
             IF #p0615_Inching2StopMode_w <> #p0615_Inching2StopMode_r THEN
               #vnWriteIndex := 1557;
               #vnWriteLength := 1;
               #vbWriteEnable := TRUE;
               #DC_DataBuffer := SHL(IN := USINT_TO_DWORD(#p0615_Inching2StopMode_w), N := 24);
               #vnWriteState := 2;
             ELSE
               #vnWriteState := 1;
             END_IF;
           34:
             IF #p0616_InposMode_w <> #p0616_InposMode_r THEN
               #vnWriteIndex := 1558;
               #vnWriteLength := 1;
               #vbWriteEnable := TRUE;
               #DC_DataBuffer := SHL(IN := USINT_TO_DWORD(#p0616_InposMode_w), N := 24);
               #vnWriteState := 2;
             ELSE
               #vnWriteState := 1;
             END_IF;
           35:
             IF #p0617_LoopLength_w <> #p0617_LoopLength_r THEN
               #vnWriteIndex := 1559;
               #vnWriteLength := 2;
               #vbWriteEnable := TRUE;
               #DC_DataBuffer := SHL(IN := INT_TO_DWORD(#p0617_LoopLength_w), N := 16);
               #vnWriteState := 2;
             ELSE
               #vnWriteState := 1;
             END_IF;
           36:
             IF #p0618_ContouringErrorLimit_w <> #p0618_ContouringErrorLimit_r THEN
               #vnWriteIndex := 1560;
               #vnWriteLength := 2;
               #vbWriteEnable := TRUE;
               #DC_DataBuffer := SHL(IN := INT_TO_DWORD(#p0618_ContouringErrorLimit_w), N := 16);
               #vnWriteState := 2;
             ELSE
               #vnWriteState := 1;
             END_IF;
           37:
             IF #p061A_Inching2Offset_w <> #p061A_Inching2Offset_r THEN
               #vnWriteIndex := 1562;
               #vnWriteLength := 1;
               #vbWriteEnable := TRUE;
               #DC_DataBuffer := SHL(IN := USINT_TO_DWORD(#p061A_Inching2Offset_w), N := 24);
               #vnWriteState := 2;
             ELSE
               #vnWriteState := 1;
             END_IF;
           38:
             IF #p061B_Inching2AccelerationType_w <> #p061B_Inching2AccelerationType_r THEN
               #vnWriteIndex := 1563;
               #vnWriteLength := 1;
               #vbWriteEnable := TRUE;
               #DC_DataBuffer := SHL(IN := USINT_TO_DWORD(#p061B_Inching2AccelerationType_w), N := 24);
               #vnWriteState := 2;
             ELSE
               #vnWriteState := 1;
             END_IF;
           39:
             IF #p061C_OffsetValue_w <> #p061C_OffsetValue_r THEN
               #vnWriteIndex := 1564;
               #vnWriteLength := 4;
               #vbWriteEnable := TRUE;
               #DC_DataBuffer := SHL(IN := DINT_TO_DWORD(#p061C_OffsetValue_w), N := 0);
               #vnWriteState := 2;
             ELSE
               #vnWriteState := 1;
             END_IF;
           40:
             IF #p0701_DisplayDivisor_w <> #p0701_DisplayDivisor_r THEN
               #vnWriteIndex := 1793;
               #vnWriteLength := 1;
               #vbWriteEnable := TRUE;
               #DC_DataBuffer := SHL(IN := USINT_TO_DWORD(#p0701_DisplayDivisor_w), N := 24);
               #vnWriteState := 2;
             ELSE
               #vnWriteState := 1;
             END_IF;
           41:
             IF #p0702_DisplayDivisorApplication_w <> #p0702_DisplayDivisorApplication_r THEN
               #vnWriteIndex := 1794;
               #vnWriteLength := 1;
               #vbWriteEnable := TRUE;
               #DC_DataBuffer := SHL(IN := USINT_TO_DWORD(#p0702_DisplayDivisorApplication_w), N := 24);
               #vnWriteState := 2;
             ELSE
               #vnWriteState := 1;
             END_IF;
           42:
             IF #p0703_DisplayOrientation_w <> #p0703_DisplayOrientation_r THEN
               #vnWriteIndex := 1795;
               #vnWriteLength := 1;
               #vbWriteEnable := TRUE;
               #DC_DataBuffer := SHL(IN := USINT_TO_DWORD(#p0703_DisplayOrientation_w), N := 24);
               #vnWriteState := 2;
             ELSE
               #vnWriteState := 1;
             END_IF;
           43:
             IF #p0704_DecimalPlaces_w <> #p0704_DecimalPlaces_r THEN
               #vnWriteIndex := 1796;
               #vnWriteLength := 1;
               #vbWriteEnable := TRUE;
               #DC_DataBuffer := SHL(IN := USINT_TO_DWORD(#p0704_DecimalPlaces_w), N := 24);
               #vnWriteState := 2;
             ELSE
               #vnWriteState := 1;
             END_IF;
           44:
             IF #p0705_DirectionIndicationFunction_w <> #p0705_DirectionIndicationFunction_r THEN
               #vnWriteIndex := 1797;
               #vnWriteLength := 1;
               #vbWriteEnable := TRUE;
               #DC_DataBuffer := SHL(IN := USINT_TO_DWORD(#p0705_DirectionIndicationFunction_w), N := 24);
               #vnWriteState := 2;
             ELSE
               #vnWriteState := 1;
             END_IF;
           45:
             IF #p0706_Display2ndLine_w <> #p0706_Display2ndLine_r THEN
               #vnWriteIndex := 1798;
               #vnWriteLength := 1;
               #vbWriteEnable := TRUE;
               #DC_DataBuffer := SHL(IN := USINT_TO_DWORD(#p0706_Display2ndLine_w), N := 24);
               #vnWriteState := 2;
             ELSE
               #vnWriteState := 1;
             END_IF;
           46:
             IF #p0707_KeyEnableTime_w <> #p0707_KeyEnableTime_r THEN
               #vnWriteIndex := 1799;
               #vnWriteLength := 1;
               #vbWriteEnable := TRUE;
               #DC_DataBuffer := SHL(IN := USINT_TO_DWORD(#p0707_KeyEnableTime_w), N := 24);
               #vnWriteState := 2;
             ELSE
               #vnWriteState := 1;
             END_IF;
           47:
             IF #p0708_KeyFunctionEnable_w <> #p0708_KeyFunctionEnable_r THEN
               #vnWriteIndex := 1800;
               #vnWriteLength := 1;
               #vbWriteEnable := TRUE;
               #DC_DataBuffer := SHL(IN := USINT_TO_DWORD(#p0708_KeyFunctionEnable_w), N := 24);
               #vnWriteState := 2;
             ELSE
               #vnWriteState := 1;
             END_IF;
           48:
             IF #p0709_PinChange_w <> #p0709_PinChange_r THEN
               #vnWriteIndex := 1801;
               #vnWriteLength := 4;
               #vbWriteEnable := TRUE;
               #DC_DataBuffer := SHL(IN := DINT_TO_DWORD(#p0709_PinChange_w), N := 0);
               #vnWriteState := 2;
             ELSE
               #vnWriteState := 1;
             END_IF;
           49:
             IF #p0801_TalTrigger_w <> #p0801_TalTrigger_r THEN
               #vnWriteIndex := 2049;
               #vnWriteLength := 2;
               #vbWriteEnable := TRUE;
               #DC_DataBuffer := SHL(IN := INT_TO_DWORD(#p0801_TalTrigger_w), N := 16);
               #vnWriteState := 2;
             ELSE
               #vnWriteState := 1;
             END_IF;
           50:
             IF #p0802_TalDirection_w <> #p0802_TalDirection_r THEN
               #vnWriteIndex := 2050;
               #vnWriteLength := 1;
               #vbWriteEnable := TRUE;
               #DC_DataBuffer := SHL(IN := USINT_TO_DWORD(#p0802_TalDirection_w), N := 24);
               #vnWriteState := 2;
             ELSE
               #vnWriteState := 1;
             END_IF;
           51:
             IF #p0922_PcmPosition1_w <> #p0922_PcmPosition1_r THEN
               #vnWriteIndex := 2338;
               #vnWriteLength := 4;
               #vbWriteEnable := TRUE;
               #DC_DataBuffer := SHL(IN := DINT_TO_DWORD(#p0922_PcmPosition1_w), N := 0);
               #vnWriteState := 2;
             ELSE
               #vnWriteState := 1;
             END_IF;
           52:
             IF #p0923_PcmPosition2_w <> #p0923_PcmPosition2_r THEN
               #vnWriteIndex := 2339;
               #vnWriteLength := 4;
               #vbWriteEnable := TRUE;
               #DC_DataBuffer := SHL(IN := DINT_TO_DWORD(#p0923_PcmPosition2_w), N := 0);
               #vnWriteState := 2;
             ELSE
               #vnWriteState := 1;
             END_IF;
           53:
             IF #p0924_PcmPosition3_w <> #p0924_PcmPosition3_r THEN
               #vnWriteIndex := 2340;
               #vnWriteLength := 4;
               #vbWriteEnable := TRUE;
               #DC_DataBuffer := SHL(IN := DINT_TO_DWORD(#p0924_PcmPosition3_w), N := 0);
               #vnWriteState := 2;
             ELSE
               #vnWriteState := 1;
             END_IF;
           54:
             IF #p0925_PcmPosition4_w <> #p0925_PcmPosition4_r THEN
               #vnWriteIndex := 2341;
               #vnWriteLength := 4;
               #vbWriteEnable := TRUE;
               #DC_DataBuffer := SHL(IN := DINT_TO_DWORD(#p0925_PcmPosition4_w), N := 0);
               #vnWriteState := 2;
             ELSE
               #vnWriteState := 1;
             END_IF;
           55:
             IF #p0926_PcmPosition5_w <> #p0926_PcmPosition5_r THEN
               #vnWriteIndex := 2342;
               #vnWriteLength := 4;
               #vbWriteEnable := TRUE;
               #DC_DataBuffer := SHL(IN := DINT_TO_DWORD(#p0926_PcmPosition5_w), N := 0);
               #vnWriteState := 2;
             ELSE
               #vnWriteState := 1;
             END_IF;
           56:
             IF #p0927_PcmPosition6_w <> #p0927_PcmPosition6_r THEN
               #vnWriteIndex := 2343;
               #vnWriteLength := 4;
               #vbWriteEnable := TRUE;
               #DC_DataBuffer := SHL(IN := DINT_TO_DWORD(#p0927_PcmPosition6_w), N := 0);
               #vnWriteState := 2;
             ELSE
               #vnWriteState := 1;
             END_IF;
           57:
             IF #p0928_PcmPosition7_w <> #p0928_PcmPosition7_r THEN
               #vnWriteIndex := 2344;
               #vnWriteLength := 4;
               #vbWriteEnable := TRUE;
               #DC_DataBuffer := SHL(IN := DINT_TO_DWORD(#p0928_PcmPosition7_w), N := 0);
               #vnWriteState := 2;
             ELSE
               #vnWriteState := 1;
             END_IF;
           58:
             IF #p0942_PcmAcceleration1_w <> #p0942_PcmAcceleration1_r THEN
               #vnWriteIndex := 2370;
               #vnWriteLength := 2;
               #vbWriteEnable := TRUE;
               #DC_DataBuffer := SHL(IN := INT_TO_DWORD(#p0942_PcmAcceleration1_w), N := 16);
               #vnWriteState := 2;
             ELSE
               #vnWriteState := 1;
             END_IF;
           59:
             IF #p0943_PcmAcceleration2_w <> #p0943_PcmAcceleration2_r THEN
               #vnWriteIndex := 2371;
               #vnWriteLength := 2;
               #vbWriteEnable := TRUE;
               #DC_DataBuffer := SHL(IN := INT_TO_DWORD(#p0943_PcmAcceleration2_w), N := 16);
               #vnWriteState := 2;
             ELSE
               #vnWriteState := 1;
             END_IF;
           60:
             IF #p0944_PcmAcceleration3_w <> #p0944_PcmAcceleration3_r THEN
               #vnWriteIndex := 2372;
               #vnWriteLength := 2;
               #vbWriteEnable := TRUE;
               #DC_DataBuffer := SHL(IN := INT_TO_DWORD(#p0944_PcmAcceleration3_w), N := 16);
               #vnWriteState := 2;
             ELSE
               #vnWriteState := 1;
             END_IF;
           61:
             IF #p0945_PcmAcceleration4_w <> #p0945_PcmAcceleration4_r THEN
               #vnWriteIndex := 2373;
               #vnWriteLength := 2;
               #vbWriteEnable := TRUE;
               #DC_DataBuffer := SHL(IN := INT_TO_DWORD(#p0945_PcmAcceleration4_w), N := 16);
               #vnWriteState := 2;
             ELSE
               #vnWriteState := 1;
             END_IF;
           62:
             IF #p0946_PcmAcceleration5_w <> #p0946_PcmAcceleration5_r THEN
               #vnWriteIndex := 2374;
               #vnWriteLength := 2;
               #vbWriteEnable := TRUE;
               #DC_DataBuffer := SHL(IN := INT_TO_DWORD(#p0946_PcmAcceleration5_w), N := 16);
               #vnWriteState := 2;
             ELSE
               #vnWriteState := 1;
             END_IF;
           63:
             IF #p0947_PcmAcceleration6_w <> #p0947_PcmAcceleration6_r THEN
               #vnWriteIndex := 2375;
               #vnWriteLength := 2;
               #vbWriteEnable := TRUE;
               #DC_DataBuffer := SHL(IN := INT_TO_DWORD(#p0947_PcmAcceleration6_w), N := 16);
               #vnWriteState := 2;
             ELSE
               #vnWriteState := 1;
             END_IF;
           64:
             IF #p0948_PcmAcceleration7_w <> #p0948_PcmAcceleration7_r THEN
               #vnWriteIndex := 2376;
               #vnWriteLength := 2;
               #vbWriteEnable := TRUE;
               #DC_DataBuffer := SHL(IN := INT_TO_DWORD(#p0948_PcmAcceleration7_w), N := 16);
               #vnWriteState := 2;
             ELSE
               #vnWriteState := 1;
             END_IF;
           65:
             IF #p0962_PcmVelocity1_w <> #p0962_PcmVelocity1_r THEN
               #vnWriteIndex := 2402;
               #vnWriteLength := 2;
               #vbWriteEnable := TRUE;
               #DC_DataBuffer := SHL(IN := INT_TO_DWORD(#p0962_PcmVelocity1_w), N := 16);
               #vnWriteState := 2;
             ELSE
               #vnWriteState := 1;
             END_IF;
           66:
             IF #p0963_PcmVelocity2_w <> #p0963_PcmVelocity2_r THEN
               #vnWriteIndex := 2403;
               #vnWriteLength := 2;
               #vbWriteEnable := TRUE;
               #DC_DataBuffer := SHL(IN := INT_TO_DWORD(#p0963_PcmVelocity2_w), N := 16);
               #vnWriteState := 2;
             ELSE
               #vnWriteState := 1;
             END_IF;
           67:
             IF #p0964_PcmVelocity3_w <> #p0964_PcmVelocity3_r THEN
               #vnWriteIndex := 2404;
               #vnWriteLength := 2;
               #vbWriteEnable := TRUE;
               #DC_DataBuffer := SHL(IN := INT_TO_DWORD(#p0964_PcmVelocity3_w), N := 16);
               #vnWriteState := 2;
             ELSE
               #vnWriteState := 1;
             END_IF;
           68:
             IF #p0965_PcmVelocity4_w <> #p0965_PcmVelocity4_r THEN
               #vnWriteIndex := 2405;
               #vnWriteLength := 2;
               #vbWriteEnable := TRUE;
               #DC_DataBuffer := SHL(IN := INT_TO_DWORD(#p0965_PcmVelocity4_w), N := 16);
               #vnWriteState := 2;
             ELSE
               #vnWriteState := 1;
             END_IF;
           69:
             IF #p0966_PcmVelocity5_w <> #p0966_PcmVelocity5_r THEN
               #vnWriteIndex := 2406;
               #vnWriteLength := 2;
               #vbWriteEnable := TRUE;
               #DC_DataBuffer := SHL(IN := INT_TO_DWORD(#p0966_PcmVelocity5_w), N := 16);
               #vnWriteState := 2;
             ELSE
               #vnWriteState := 1;
             END_IF;
           70:
             IF #p0967_PcmVelocity6_w <> #p0967_PcmVelocity6_r THEN
               #vnWriteIndex := 2407;
               #vnWriteLength := 2;
               #vbWriteEnable := TRUE;
               #DC_DataBuffer := SHL(IN := INT_TO_DWORD(#p0967_PcmVelocity6_w), N := 16);
               #vnWriteState := 2;
             ELSE
               #vnWriteState := 1;
             END_IF;
           71:
             IF #p0968_PcmVelocity7_w <> #p0968_PcmVelocity7_r THEN
               #vnWriteIndex := 2408;
               #vnWriteLength := 2;
               #vbWriteEnable := TRUE;
               #DC_DataBuffer := SHL(IN := INT_TO_DWORD(#p0968_PcmVelocity7_w), N := 16);
               #vnWriteState := 2;
             ELSE
               #vnWriteState := 1;
             END_IF;
           72:
             IF #p0982_PcmDeceleration1_w <> #p0982_PcmDeceleration1_r THEN
               #vnWriteIndex := 2434;
               #vnWriteLength := 2;
               #vbWriteEnable := TRUE;
               #DC_DataBuffer := SHL(IN := INT_TO_DWORD(#p0982_PcmDeceleration1_w), N := 16);
               #vnWriteState := 2;
             ELSE
               #vnWriteState := 1;
             END_IF;
           73:
             IF #p0983_PcmDeceleration2_w <> #p0983_PcmDeceleration2_r THEN
               #vnWriteIndex := 2435;
               #vnWriteLength := 2;
               #vbWriteEnable := TRUE;
               #DC_DataBuffer := SHL(IN := INT_TO_DWORD(#p0983_PcmDeceleration2_w), N := 16);
               #vnWriteState := 2;
             ELSE
               #vnWriteState := 1;
             END_IF;
           74:
             IF #p0984_PcmDeceleration3_w <> #p0984_PcmDeceleration3_r THEN
               #vnWriteIndex := 2436;
               #vnWriteLength := 2;
               #vbWriteEnable := TRUE;
               #DC_DataBuffer := SHL(IN := INT_TO_DWORD(#p0984_PcmDeceleration3_w), N := 16);
               #vnWriteState := 2;
             ELSE
               #vnWriteState := 1;
             END_IF;
           75:
             IF #p0985_PcmDeceleration4_w <> #p0985_PcmDeceleration4_r THEN
               #vnWriteIndex := 2437;
               #vnWriteLength := 2;
               #vbWriteEnable := TRUE;
               #DC_DataBuffer := SHL(IN := INT_TO_DWORD(#p0985_PcmDeceleration4_w), N := 16);
               #vnWriteState := 2;
             ELSE
               #vnWriteState := 1;
             END_IF;
           76:
             IF #p0986_PcmDeceleration5_w <> #p0986_PcmDeceleration5_r THEN
               #vnWriteIndex := 2438;
               #vnWriteLength := 2;
               #vbWriteEnable := TRUE;
               #DC_DataBuffer := SHL(IN := INT_TO_DWORD(#p0986_PcmDeceleration5_w), N := 16);
               #vnWriteState := 2;
             ELSE
               #vnWriteState := 1;
             END_IF;
           77:
             IF #p0987_PcmDeceleration6_w <> #p0987_PcmDeceleration6_r THEN
               #vnWriteIndex := 2439;
               #vnWriteLength := 2;
               #vbWriteEnable := TRUE;
               #DC_DataBuffer := SHL(IN := INT_TO_DWORD(#p0987_PcmDeceleration6_w), N := 16);
               #vnWriteState := 2;
             ELSE
               #vnWriteState := 1;
             END_IF;
           78:
             IF #p0988_PcmDeceleration7_w <> #p0988_PcmDeceleration7_r THEN
               #vnWriteIndex := 2440;
               #vnWriteLength := 2;
               #vbWriteEnable := TRUE;
               #DC_DataBuffer := SHL(IN := INT_TO_DWORD(#p0988_PcmDeceleration7_w), N := 16);
               #vnWriteState := 2;
             ELSE
               #vnWriteState := 1;
             END_IF;
           79:
             IF #p0B21_Configuration_w <> #p0B21_Configuration_r THEN
               #vnWriteIndex := 2849;
               #vnWriteLength := 2;
               #vbWriteEnable := TRUE;
               #DC_DataBuffer := SHL(IN := UINT_TO_DWORD(#p0B21_Configuration_w), N := 16);
               #vnWriteState := 2;
             ELSE
               #vnWriteState := 1;
             END_IF;
           80:
             IF #p0C01_Scommand_w <> #p0C01_Scommand_r THEN
               #vnWriteIndex := 3073;
               #vnWriteLength := 1;
               #vbWriteEnable := TRUE;
               #DC_DataBuffer := SHL(IN := USINT_TO_DWORD(#p0C01_Scommand_w), N := 24);
               #vnWriteState := 2;
             ELSE
               #vnWriteState := 1;
             END_IF;
         END_CASE;
       END_IF;
     2: // wait for end of WRREC
       IF #vbOsfWriteBusy THEN
         #vnWriteState := 3;
       END_IF;
     3: // Check for errors, copy output
       IF #vbWriteError THEN
         #bsBusy := FALSE;
         #bsError := TRUE;
         #bsDone := FALSE;
         #nStatus := #vnWriteStatus;
         #vnWriteCounter := 0;
         #vnWriteState := 0;
         #vbWriteEnable := FALSE;
       ELSIF #vbWriteDone THEN
       (* Transfer successful *)
         #nStatus := #vnWriteStatus;
         #vbWriteEnable := FALSE;

         CASE #vnWriteCounter OF
           1:
             #p0221_ServiceInterfaceBaudRate_r := #p0221_ServiceInterfaceBaudRate_w;
           2:
             #p0222_GenMapParam_r := #p0222_GenMapParam_w;
           3:
             #p0241_PeakCurrentLimit_r := #p0241_PeakCurrentLimit_w;
           4:
             #p0242_PeakCurrentTime_r := #p0242_PeakCurrentTime_w;
           5:
             #p0243_ContinuousCurrent_r := #p0243_ContinuousCurrent_w;
           6:
             #p0301_DigitalOutput1Functionality_r := #p0301_DigitalOutput1Functionality_w;
           7:
             #p0303_DigitalOutputsPolarity_r := #p0303_DigitalOutputsPolarity_w;
           8:
             #p0401_DigitalInput1Functionality_r := #p0401_DigitalInput1Functionality_w;
           9:
             #p0402_DigitalInput2Functionality_r := #p0402_DigitalInput2Functionality_w;
           10:
             #p0403_DigitalInput3Functionality_r := #p0403_DigitalInput3Functionality_w;
           11:
             #p0404_DigitalInput4Functionality_r := #p0404_DigitalInput4Functionality_w;
           12:
             #p0406_DigitalInputsPolarity_r := #p0406_DigitalInputsPolarity_w;
           13:
             #p0601_ControllerParameterP_r := #p0601_ControllerParameterP_w;
           14:
             #p0602_ControllerParameterI_r := #p0602_ControllerParameterI_w;
           15:
             #p0603_ControllerParameterD_r := #p0603_ControllerParameterD_w;
           16:
             #p0604_APos_r := #p0604_APos_w;
           17:
             #p0605_VPos_r := #p0605_VPos_w;
           18:
             #p0606_DPos_r := #p0606_DPos_w;
           19:
             #p0607_ARot_r := #p0607_ARot_w;
           20:
             #p0608_AInch_r := #p0608_AInch_w;
           21:
             #p0609_VInch_r := #p0609_VInch_w;
           22:
             #p060A_PosWindow_r := #p060A_PosWindow_w;
           23:
             #p060B_GearRatioNumerator_r := #p060B_GearRatioNumerator_w;
           24:
             #p060C_GearRatioDenominator_r := #p060C_GearRatioDenominator_w;
           25:
             #p060D_SpindlePitch_r := #p060D_SpindlePitch_w;
           26:
             #p060E_CalibrationValue_r := #p060E_CalibrationValue_w;
           27:
             #p060F_SoftwareLimit1_r := #p060F_SoftwareLimit1_w;
           28:
             #p0610_SoftwareLimit2_r := #p0610_SoftwareLimit2_w;
           29:
             #p0611_DeltaInch_r := #p0611_DeltaInch_w;
           30:
             #p0612_SenseOfRotation_r := #p0612_SenseOfRotation_w;
           31:
             #p0613_PosType_r := #p0613_PosType_w;
           32:
             #p0614_OperatingMode_r := #p0614_OperatingMode_w;
           33:
             #p0615_Inching2StopMode_r := #p0615_Inching2StopMode_w;
           34:
             #p0616_InposMode_r := #p0616_InposMode_w;
           35:
             #p0617_LoopLength_r := #p0617_LoopLength_w;
           36:
             #p0618_ContouringErrorLimit_r := #p0618_ContouringErrorLimit_w;
           37:
             #p061A_Inching2Offset_r := #p061A_Inching2Offset_w;
           38:
             #p061B_Inching2AccelerationType_r := #p061B_Inching2AccelerationType_w;
           39:
             #p061C_OffsetValue_r := #p061C_OffsetValue_w;
           40:
             #p0701_DisplayDivisor_r := #p0701_DisplayDivisor_w;
           41:
             #p0702_DisplayDivisorApplication_r := #p0702_DisplayDivisorApplication_w;
           42:
             #p0703_DisplayOrientation_r := #p0703_DisplayOrientation_w;
           43:
             #p0704_DecimalPlaces_r := #p0704_DecimalPlaces_w;
           44:
             #p0705_DirectionIndicationFunction_r := #p0705_DirectionIndicationFunction_w;
           45:
             #p0706_Display2ndLine_r := #p0706_Display2ndLine_w;
           46:
             #p0707_KeyEnableTime_r := #p0707_KeyEnableTime_w;
           47:
             #p0708_KeyFunctionEnable_r := #p0708_KeyFunctionEnable_w;
           48:
             #p0709_PinChange_r := #p0709_PinChange_w;
           49:
             #p0801_TalTrigger_r := #p0801_TalTrigger_w;
           50:
             #p0802_TalDirection_r := #p0802_TalDirection_w;
           51:
             #p0922_PcmPosition1_r := #p0922_PcmPosition1_w;
           52:
             #p0923_PcmPosition2_r := #p0923_PcmPosition2_w;
           53:
             #p0924_PcmPosition3_r := #p0924_PcmPosition3_w;
           54:
             #p0925_PcmPosition4_r := #p0925_PcmPosition4_w;
           55:
             #p0926_PcmPosition5_r := #p0926_PcmPosition5_w;
           56:
             #p0927_PcmPosition6_r := #p0927_PcmPosition6_w;
           57:
             #p0928_PcmPosition7_r := #p0928_PcmPosition7_w;
           58:
             #p0942_PcmAcceleration1_r := #p0942_PcmAcceleration1_w;
           59:
             #p0943_PcmAcceleration2_r := #p0943_PcmAcceleration2_w;
           60:
             #p0944_PcmAcceleration3_r := #p0944_PcmAcceleration3_w;
           61:
             #p0945_PcmAcceleration4_r := #p0945_PcmAcceleration4_w;
           62:
             #p0946_PcmAcceleration5_r := #p0946_PcmAcceleration5_w;
           63:
             #p0947_PcmAcceleration6_r := #p0947_PcmAcceleration6_w;
           64:
             #p0948_PcmAcceleration7_r := #p0948_PcmAcceleration7_w;
           65:
             #p0962_PcmVelocity1_r := #p0962_PcmVelocity1_w;
           66:
             #p0963_PcmVelocity2_r := #p0963_PcmVelocity2_w;
           67:
             #p0964_PcmVelocity3_r := #p0964_PcmVelocity3_w;
           68:
             #p0965_PcmVelocity4_r := #p0965_PcmVelocity4_w;
           69:
             #p0966_PcmVelocity5_r := #p0966_PcmVelocity5_w;
           70:
             #p0967_PcmVelocity6_r := #p0967_PcmVelocity6_w;
           71:
             #p0968_PcmVelocity7_r := #p0968_PcmVelocity7_w;
           72:
             #p0982_PcmDeceleration1_r := #p0982_PcmDeceleration1_w;
           73:
             #p0983_PcmDeceleration2_r := #p0983_PcmDeceleration2_w;
           74:
             #p0984_PcmDeceleration3_r := #p0984_PcmDeceleration3_w;
           75:
             #p0985_PcmDeceleration4_r := #p0985_PcmDeceleration4_w;
           76:
             #p0986_PcmDeceleration5_r := #p0986_PcmDeceleration5_w;
           77:
             #p0987_PcmDeceleration6_r := #p0987_PcmDeceleration6_w;
           78:
             #p0988_PcmDeceleration7_r := #p0988_PcmDeceleration7_w;
           79:
             #p0B21_Configuration_r := #p0B21_Configuration_w;
           80:
             #p0C01_Scommand_r := 0; // set always to zero
         END_CASE;
         #vnWriteState := 1;
       END_IF;
   END_CASE;

   // Handle Parameter Copy Command
   CASE #vnCopyState OF
     0: // wait for rising edge at input bcStartCopy
       IF #vbOsrStartCopy AND (#vnReadState = 0) AND (#vnWriteState = 0) THEN
         #bsBusy := TRUE;
         #bsError := FALSE;
         #bsDone := FALSE;
         #nStatus := 0;
         #nCounterCopy := 0;
         #vnCopyCounter := 0;
         #vnCopyState := 1;
       END_IF;
     1: // Start COPY
       #vnCopyCounter := #vnCopyCounter + 1;
       IF (#vnCopyCounter > 80) THEN
         // End of copy cycle
         #bsBusy := FALSE;
         #bsError := FALSE;
         #bsDone := TRUE;
         #nStatus := 0;
         #nCounterCopy := 0;
         #vnCopyCounter := 0;
         #vnCopyState := 0;
       ELSE
       (* output counter_copy *)
         #nCounterCopy := #vnCopyCounter;
         CASE #vnCopyCounter OF
           1:
             #p0221_ServiceInterfaceBaudRate_w := #p0221_ServiceInterfaceBaudRate_r;
           2:
             #p0222_GenMapParam_w := #p0222_GenMapParam_r;
           3:
             #p0241_PeakCurrentLimit_w := #p0241_PeakCurrentLimit_r;
           4:
             #p0242_PeakCurrentTime_w := #p0242_PeakCurrentTime_r;
           5:
             #p0243_ContinuousCurrent_w := #p0243_ContinuousCurrent_r;
           6:
             #p0301_DigitalOutput1Functionality_w := #p0301_DigitalOutput1Functionality_r;
           7:
             #p0303_DigitalOutputsPolarity_w := #p0303_DigitalOutputsPolarity_r;
           8:
             #p0401_DigitalInput1Functionality_w := #p0401_DigitalInput1Functionality_r;
           9:
             #p0402_DigitalInput2Functionality_w := #p0402_DigitalInput2Functionality_r;
           10:
             #p0403_DigitalInput3Functionality_w := #p0403_DigitalInput3Functionality_r;
           11:
             #p0404_DigitalInput4Functionality_w := #p0404_DigitalInput4Functionality_r;
           12:
             #p0406_DigitalInputsPolarity_w := #p0406_DigitalInputsPolarity_r;
           13:
             #p0601_ControllerParameterP_w := #p0601_ControllerParameterP_r;
           14:
             #p0602_ControllerParameterI_w := #p0602_ControllerParameterI_r;
           15:
             #p0603_ControllerParameterD_w := #p0603_ControllerParameterD_r;
           16:
             #p0604_APos_w := #p0604_APos_r;
           17:
             #p0605_VPos_w := #p0605_VPos_r;
           18:
             #p0606_DPos_w := #p0606_DPos_r;
           19:
             #p0607_ARot_w := #p0607_ARot_r;
           20:
             #p0608_AInch_w := #p0608_AInch_r;
           21:
             #p0609_VInch_w := #p0609_VInch_r;
           22:
             #p060A_PosWindow_w := #p060A_PosWindow_r;
           23:
             #p060B_GearRatioNumerator_w := #p060B_GearRatioNumerator_r;
           24:
             #p060C_GearRatioDenominator_w := #p060C_GearRatioDenominator_r;
           25:
             #p060D_SpindlePitch_w := #p060D_SpindlePitch_r;
           26:
             #p060E_CalibrationValue_w := #p060E_CalibrationValue_r;
           27:
             #p060F_SoftwareLimit1_w := #p060F_SoftwareLimit1_r;
           28:
             #p0610_SoftwareLimit2_w := #p0610_SoftwareLimit2_r;
           29:
             #p0611_DeltaInch_w := #p0611_DeltaInch_r;
           30:
             #p0612_SenseOfRotation_w := #p0612_SenseOfRotation_r;
           31:
             #p0613_PosType_w := #p0613_PosType_r;
           32:
             #p0614_OperatingMode_w := #p0614_OperatingMode_r;
           33:
             #p0615_Inching2StopMode_w := #p0615_Inching2StopMode_r;
           34:
             #p0616_InposMode_w := #p0616_InposMode_r;
           35:
             #p0617_LoopLength_w := #p0617_LoopLength_r;
           36:
             #p0618_ContouringErrorLimit_w := #p0618_ContouringErrorLimit_r;
           37:
             #p061A_Inching2Offset_w := #p061A_Inching2Offset_r;
           38:
             #p061B_Inching2AccelerationType_w := #p061B_Inching2AccelerationType_r;
           39:
             #p061C_OffsetValue_w := #p061C_OffsetValue_r;
           40:
             #p0701_DisplayDivisor_w := #p0701_DisplayDivisor_r;
           41:
             #p0702_DisplayDivisorApplication_w := #p0702_DisplayDivisorApplication_r;
           42:
             #p0703_DisplayOrientation_w := #p0703_DisplayOrientation_r;
           43:
             #p0704_DecimalPlaces_w := #p0704_DecimalPlaces_r;
           44:
             #p0705_DirectionIndicationFunction_w := #p0705_DirectionIndicationFunction_r;
           45:
             #p0706_Display2ndLine_w := #p0706_Display2ndLine_r;
           46:
             #p0707_KeyEnableTime_w := #p0707_KeyEnableTime_r;
           47:
             #p0708_KeyFunctionEnable_w := #p0708_KeyFunctionEnable_r;
           48:
             #p0709_PinChange_w := #p0709_PinChange_r;
           49:
             #p0801_TalTrigger_w := #p0801_TalTrigger_r;
           50:
             #p0802_TalDirection_w := #p0802_TalDirection_r;
           51:
             #p0922_PcmPosition1_w := #p0922_PcmPosition1_r;
           52:
             #p0923_PcmPosition2_w := #p0923_PcmPosition2_r;
           53:
             #p0924_PcmPosition3_w := #p0924_PcmPosition3_r;
           54:
             #p0925_PcmPosition4_w := #p0925_PcmPosition4_r;
           55:
             #p0926_PcmPosition5_w := #p0926_PcmPosition5_r;
           56:
             #p0927_PcmPosition6_w := #p0927_PcmPosition6_r;
           57:
             #p0928_PcmPosition7_w := #p0928_PcmPosition7_r;
           58:
             #p0942_PcmAcceleration1_w := #p0942_PcmAcceleration1_r;
           59:
             #p0943_PcmAcceleration2_w := #p0943_PcmAcceleration2_r;
           60:
             #p0944_PcmAcceleration3_w := #p0944_PcmAcceleration3_r;
           61:
             #p0945_PcmAcceleration4_w := #p0945_PcmAcceleration4_r;
           62:
             #p0946_PcmAcceleration5_w := #p0946_PcmAcceleration5_r;
           63:
             #p0947_PcmAcceleration6_w := #p0947_PcmAcceleration6_r;
           64:
             #p0948_PcmAcceleration7_w := #p0948_PcmAcceleration7_r;
           65:
             #p0962_PcmVelocity1_w := #p0962_PcmVelocity1_r;
           66:
             #p0963_PcmVelocity2_w := #p0963_PcmVelocity2_r;
           67:
             #p0964_PcmVelocity3_w := #p0964_PcmVelocity3_r;
           68:
             #p0965_PcmVelocity4_w := #p0965_PcmVelocity4_r;
           69:
             #p0966_PcmVelocity5_w := #p0966_PcmVelocity5_r;
           70:
             #p0967_PcmVelocity6_w := #p0967_PcmVelocity6_r;
           71:
             #p0968_PcmVelocity7_w := #p0968_PcmVelocity7_r;
           72:
             #p0982_PcmDeceleration1_w := #p0982_PcmDeceleration1_r;
           73:
             #p0983_PcmDeceleration2_w := #p0983_PcmDeceleration2_r;
           74:
             #p0984_PcmDeceleration3_w := #p0984_PcmDeceleration3_r;
           75:
             #p0985_PcmDeceleration4_w := #p0985_PcmDeceleration4_r;
           76:
             #p0986_PcmDeceleration5_w := #p0986_PcmDeceleration5_r;
           77:
             #p0987_PcmDeceleration6_w := #p0987_PcmDeceleration6_r;
           78:
             #p0988_PcmDeceleration7_w := #p0988_PcmDeceleration7_r;
           79:
             #p0B21_Configuration_w := #p0B21_Configuration_r;
           80:
             #p0C01_Scommand_w := #p0C01_Scommand_r;
         END_CASE;
       END_IF;
   END_CASE;

   // Read Record
   #fbRDREC1(ID := #DC_nHwId,
             INDEX := #vnReadIndex,
             MLEN := 4,
             REQ := #vbReadEnable,
             RECORD := #varrDataBuffer,
             VALID => #vbReadValid,
             BUSY => #vbReadBusy,
             ERROR => #vbReadError,
             STATUS => #vnReadStatus,
             LEN => #vnReadLength);

   // Write Record
   #fbWRREC_1(ID := #DC_nHwId,
              INDEX := #vnWriteIndex,
              LEN := #vnWriteLength,
              REQ := #vbWriteEnable,
              RECORD := #varrDataBuffer,
              BUSY => #vbWriteBusy,
              ERROR => #vbWriteError,
              DONE => #vbWriteDone,
              STATUS => #vnWriteStatus);

   // vbReadBusy: falling edge
   #vbOsfReadBusy := NOT #vbReadBusy AND #vbMemReadBusy;
   #vbMemReadBusy := #vbReadBusy;

   // #vbWriteBusy: falling edge 
   #vbOsfWriteBusy := NOT #vbWriteBusy AND #vbMemWriteBusy;
   #vbMemWriteBusy := #vbWriteBusy;

   // bcStartRead: rising edge
   #vbOsrStartRead := #bcStartRead AND NOT #vbMemStartRead;
   #vbMemStartRead := #bcStartRead;

   // bcStartWrite: rising edge
   #vbOsrStartWrite := #bcStartWrite AND NOT #vbMemStartWrite;
   #vbMemStartWrite := #bcStartWrite;

   // bcStartCopy: rising edge
   #vbOsrStartCopy := #bcStartCopy AND NOT #vbMemStartCopy;
   #vbMemStartCopy := #bcStartCopy;
END_FUNCTION_BLOCK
